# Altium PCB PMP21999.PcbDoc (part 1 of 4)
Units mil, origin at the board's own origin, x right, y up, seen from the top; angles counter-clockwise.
Board outline 7450 x 5800 mil, 6 copper layers (Top Layer, Signal Layer 3, Signal Layer 1, Signal Layer 2, Signal Layer 4, Bottom Layer), stack 66 mil thick; 237 components, 96 nets, 712 pads, 268 vias.
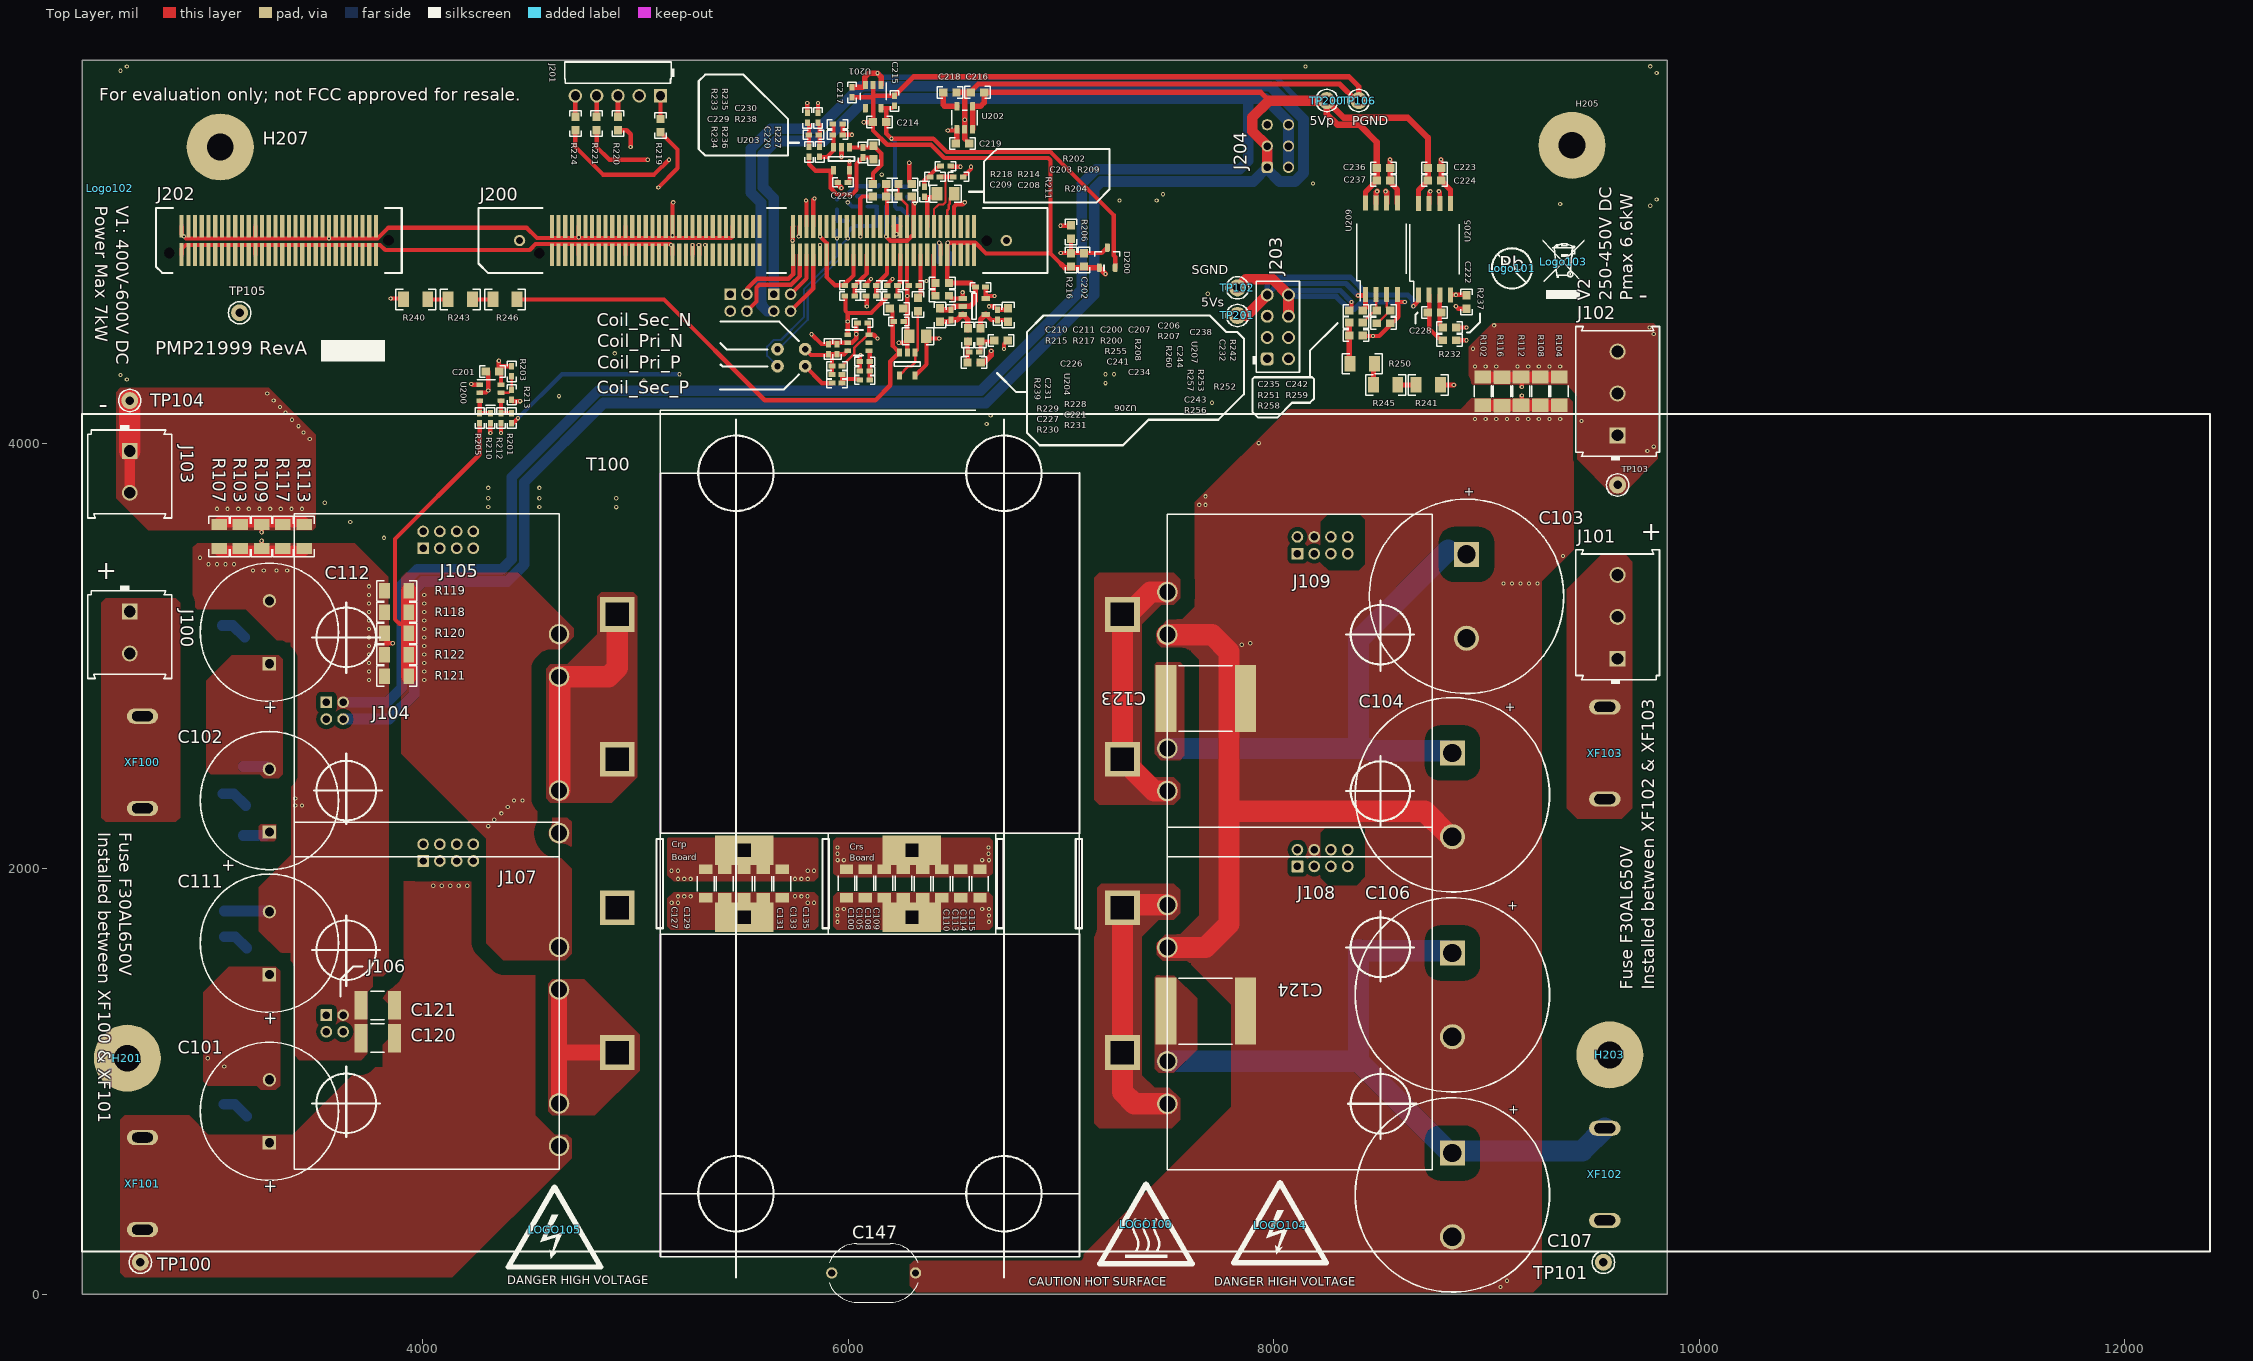
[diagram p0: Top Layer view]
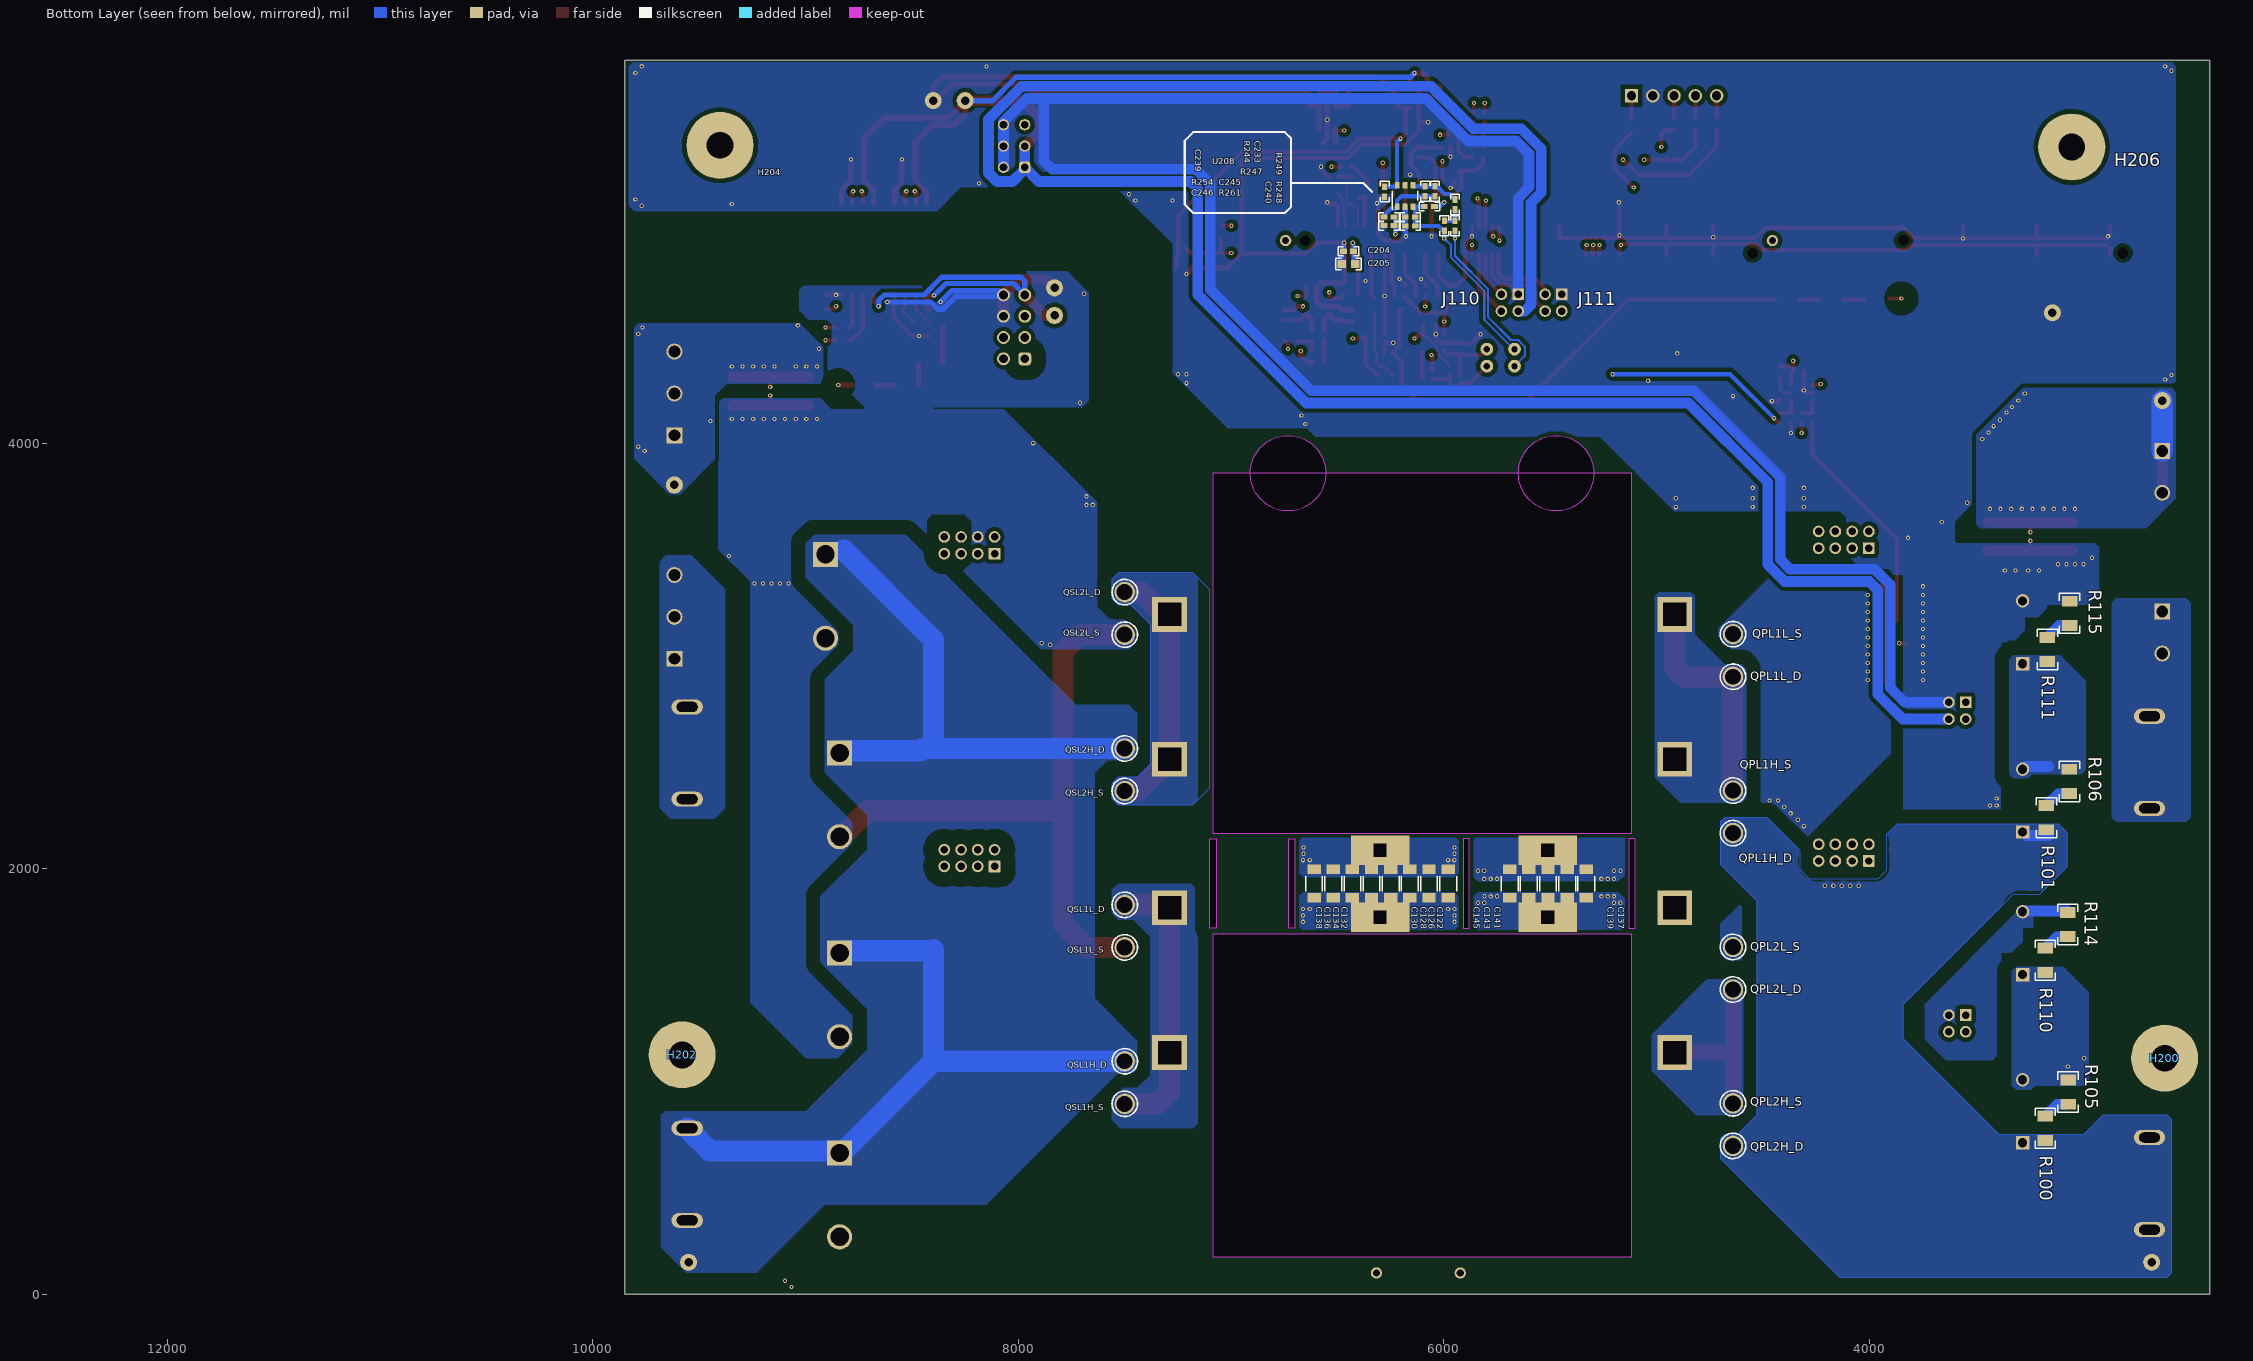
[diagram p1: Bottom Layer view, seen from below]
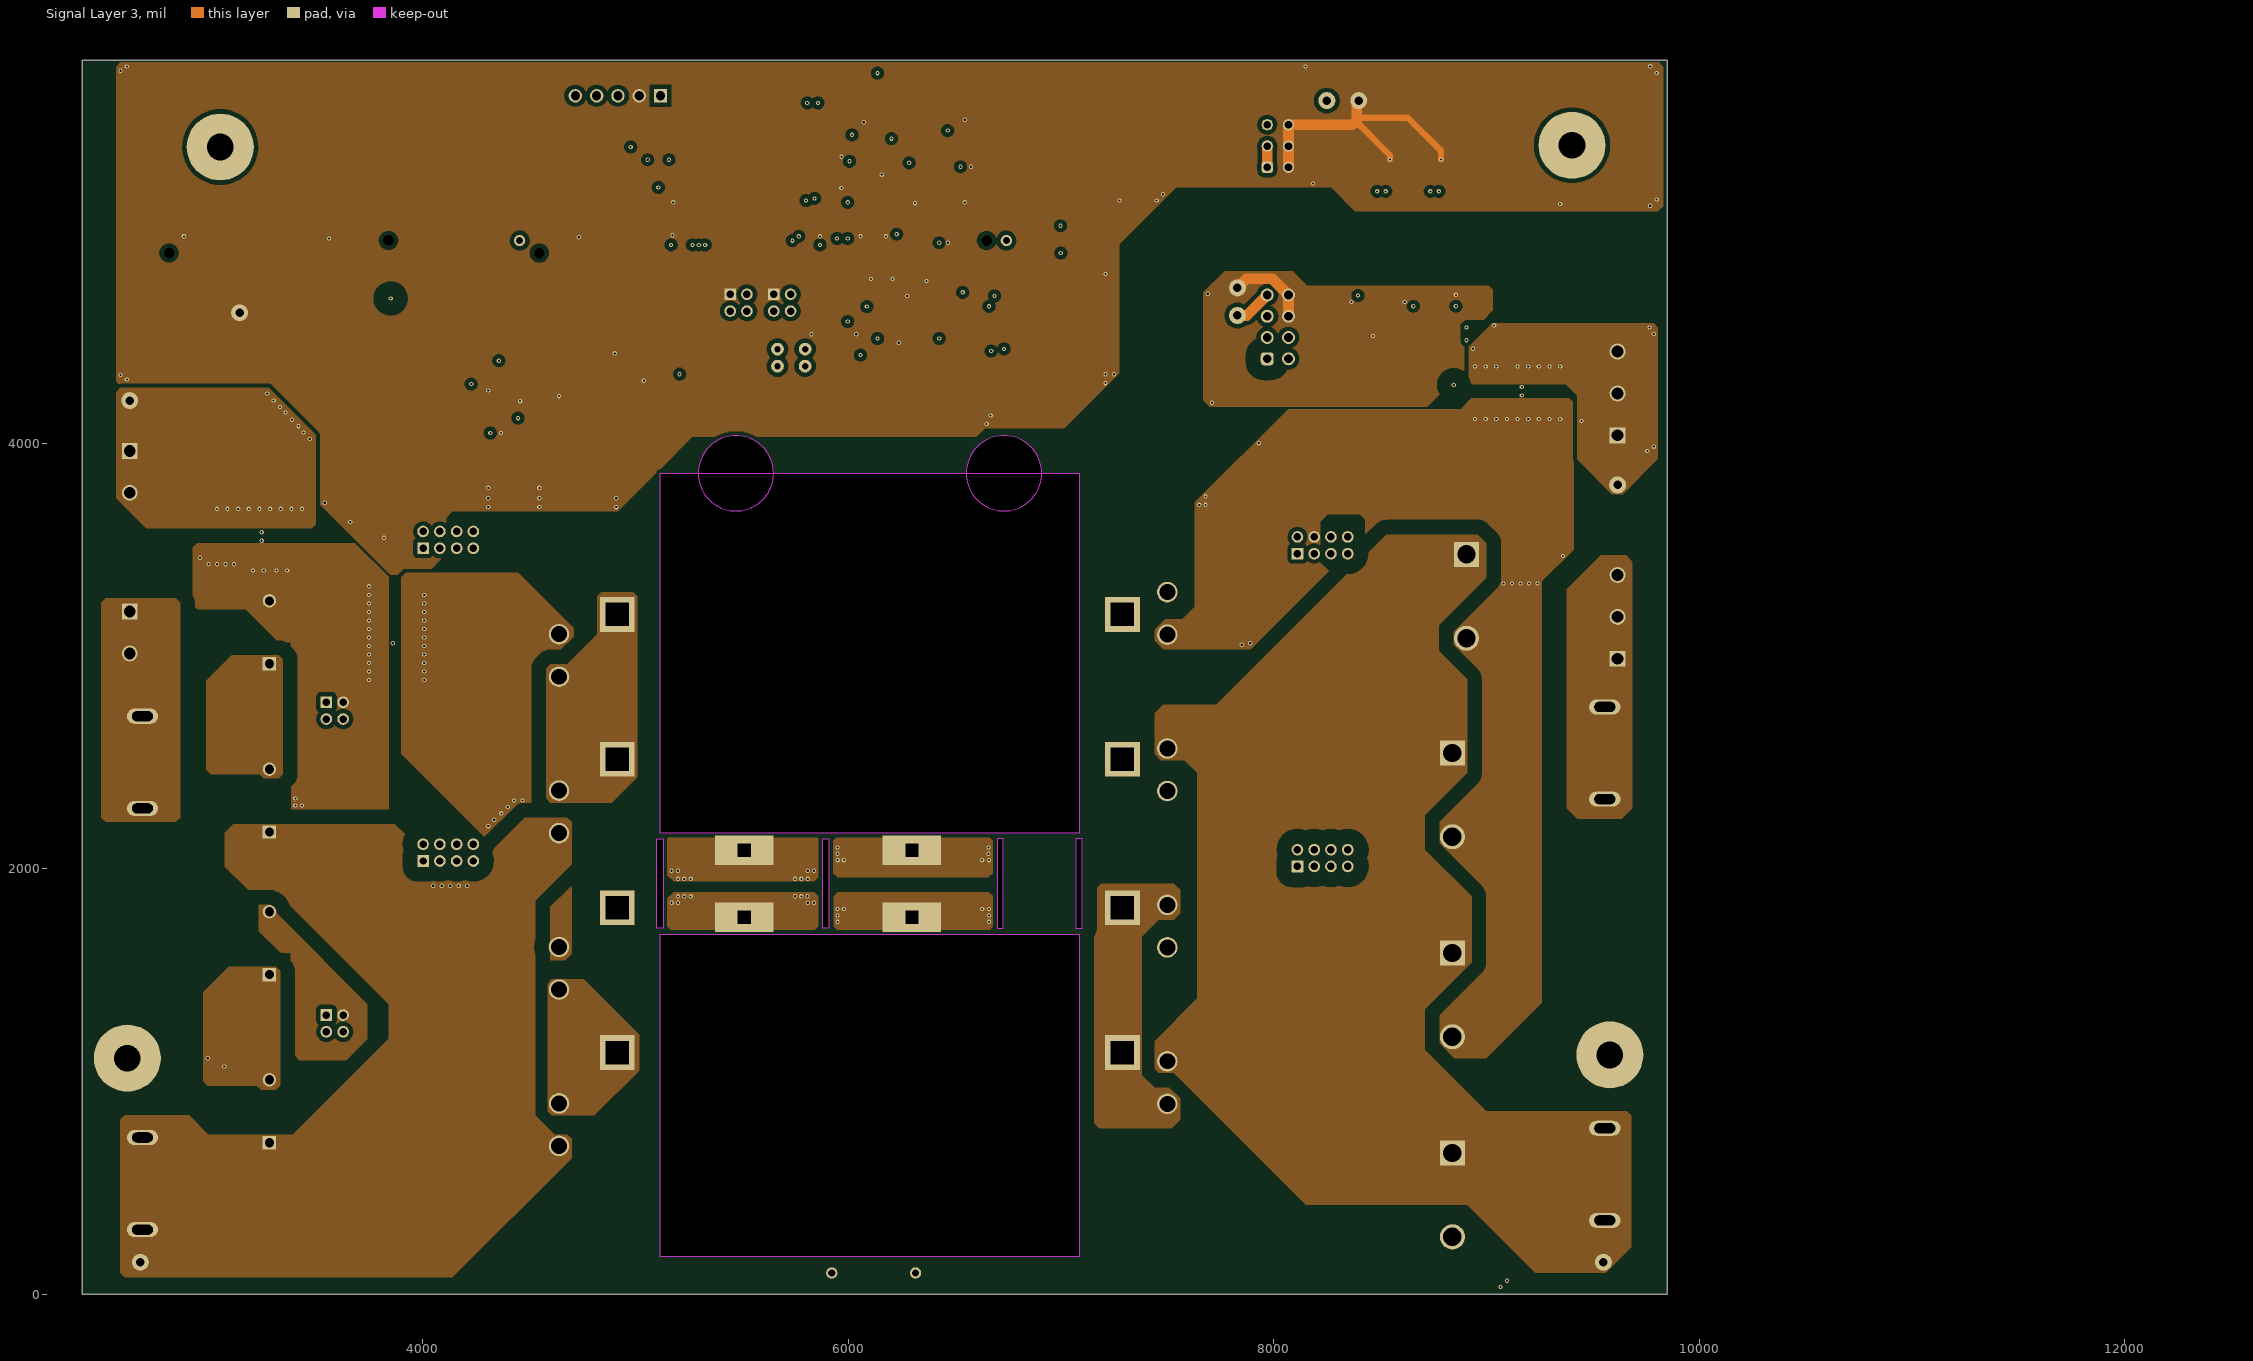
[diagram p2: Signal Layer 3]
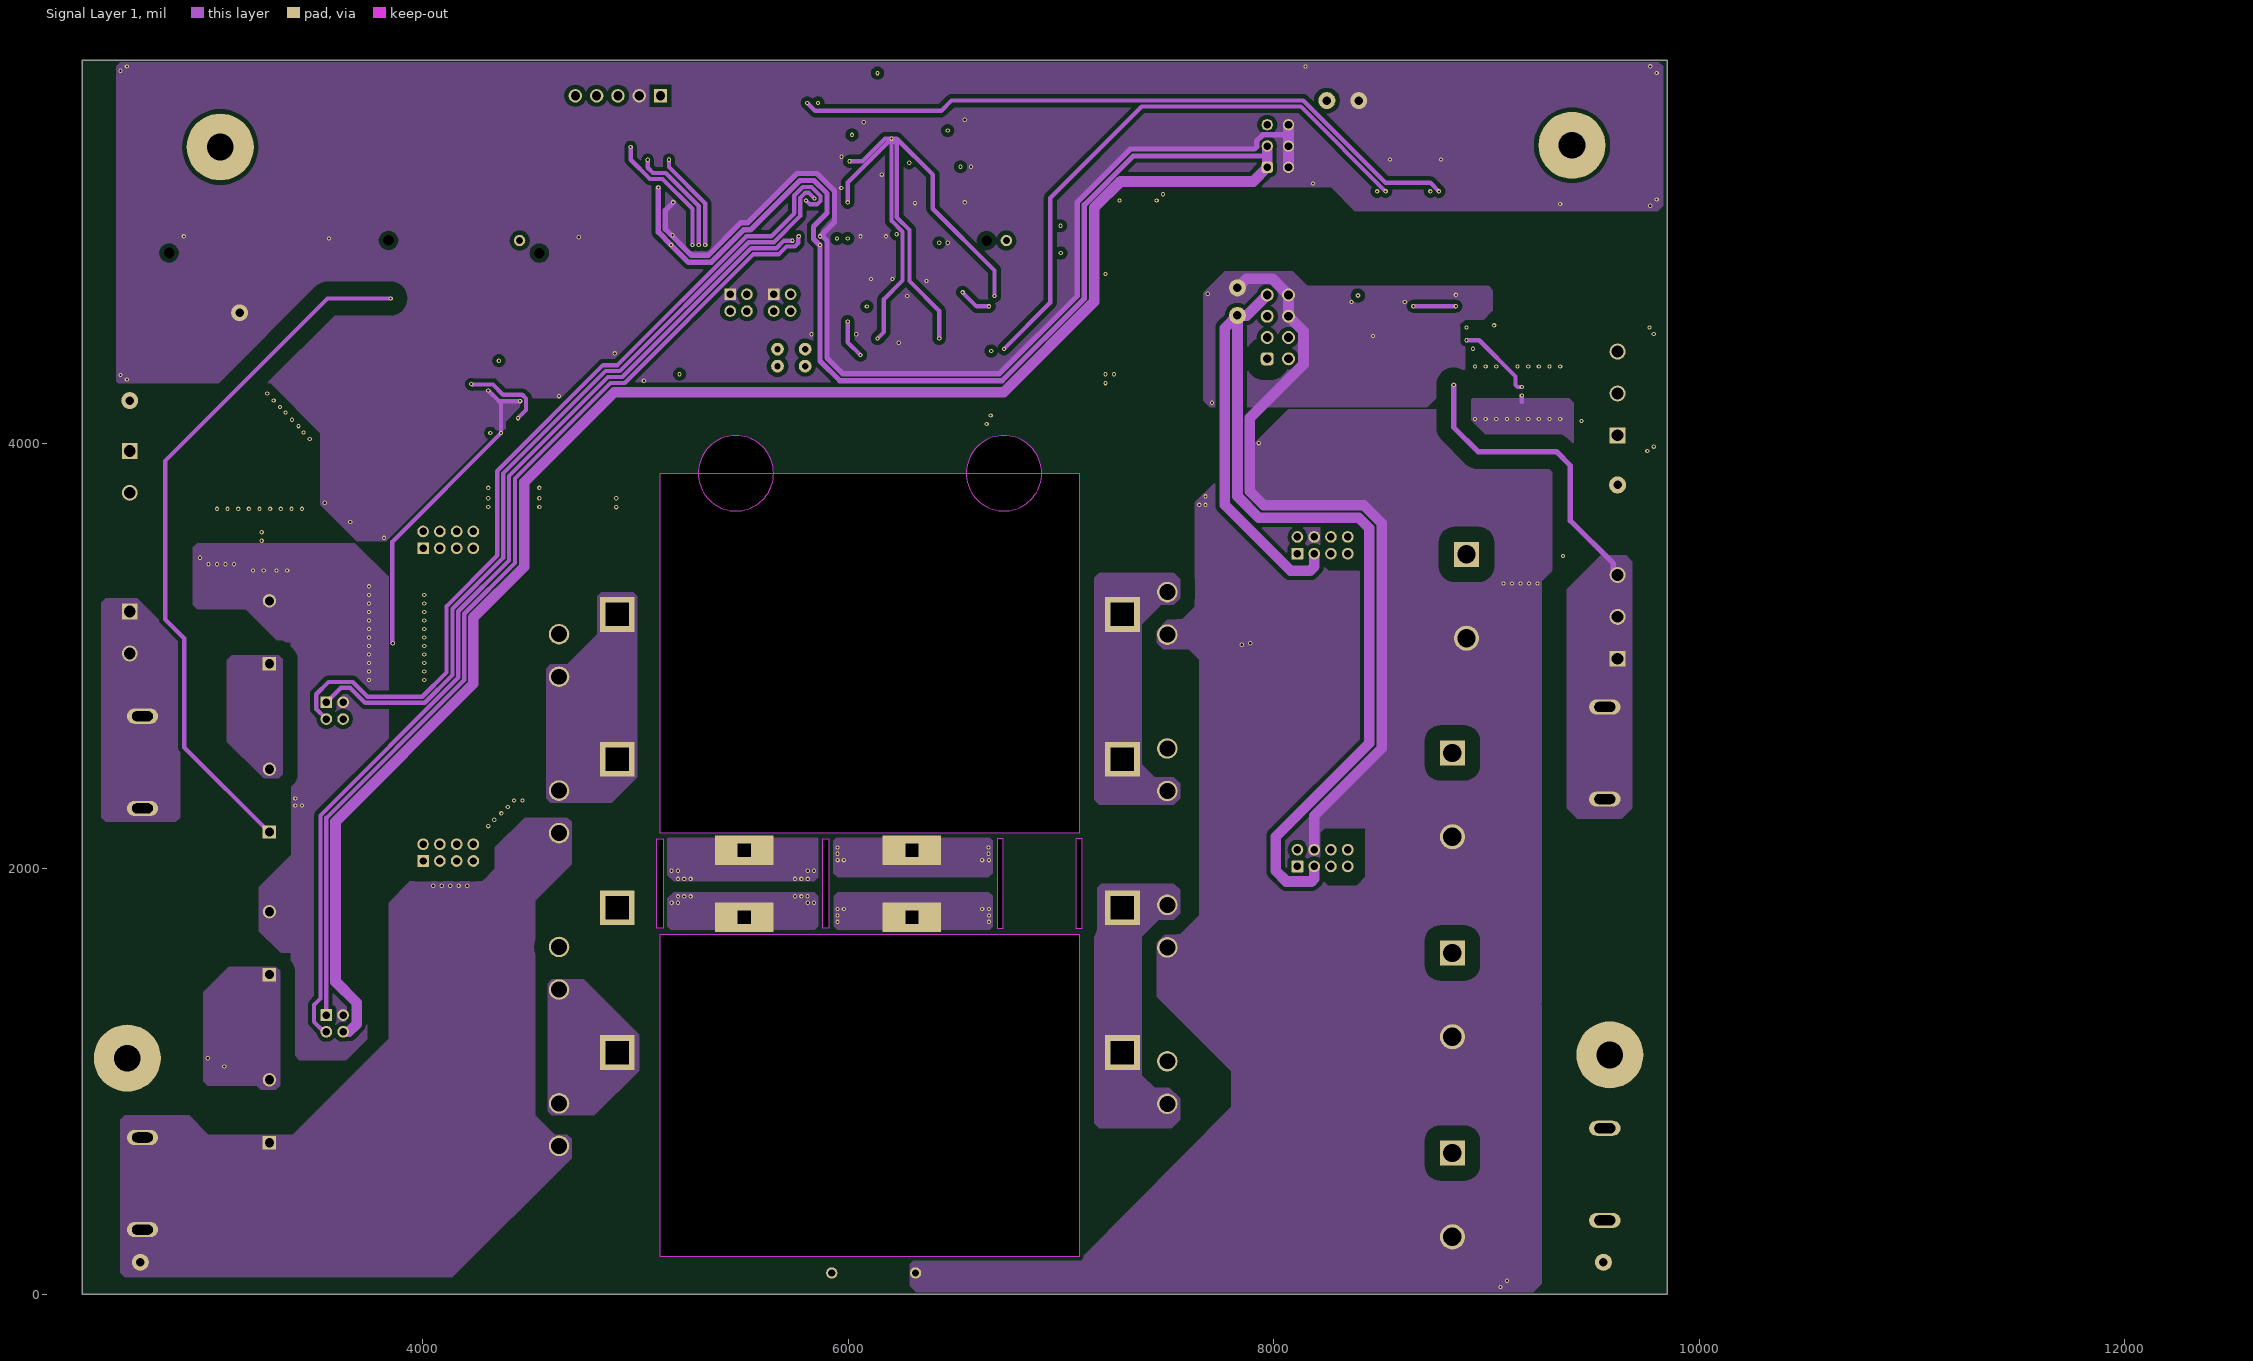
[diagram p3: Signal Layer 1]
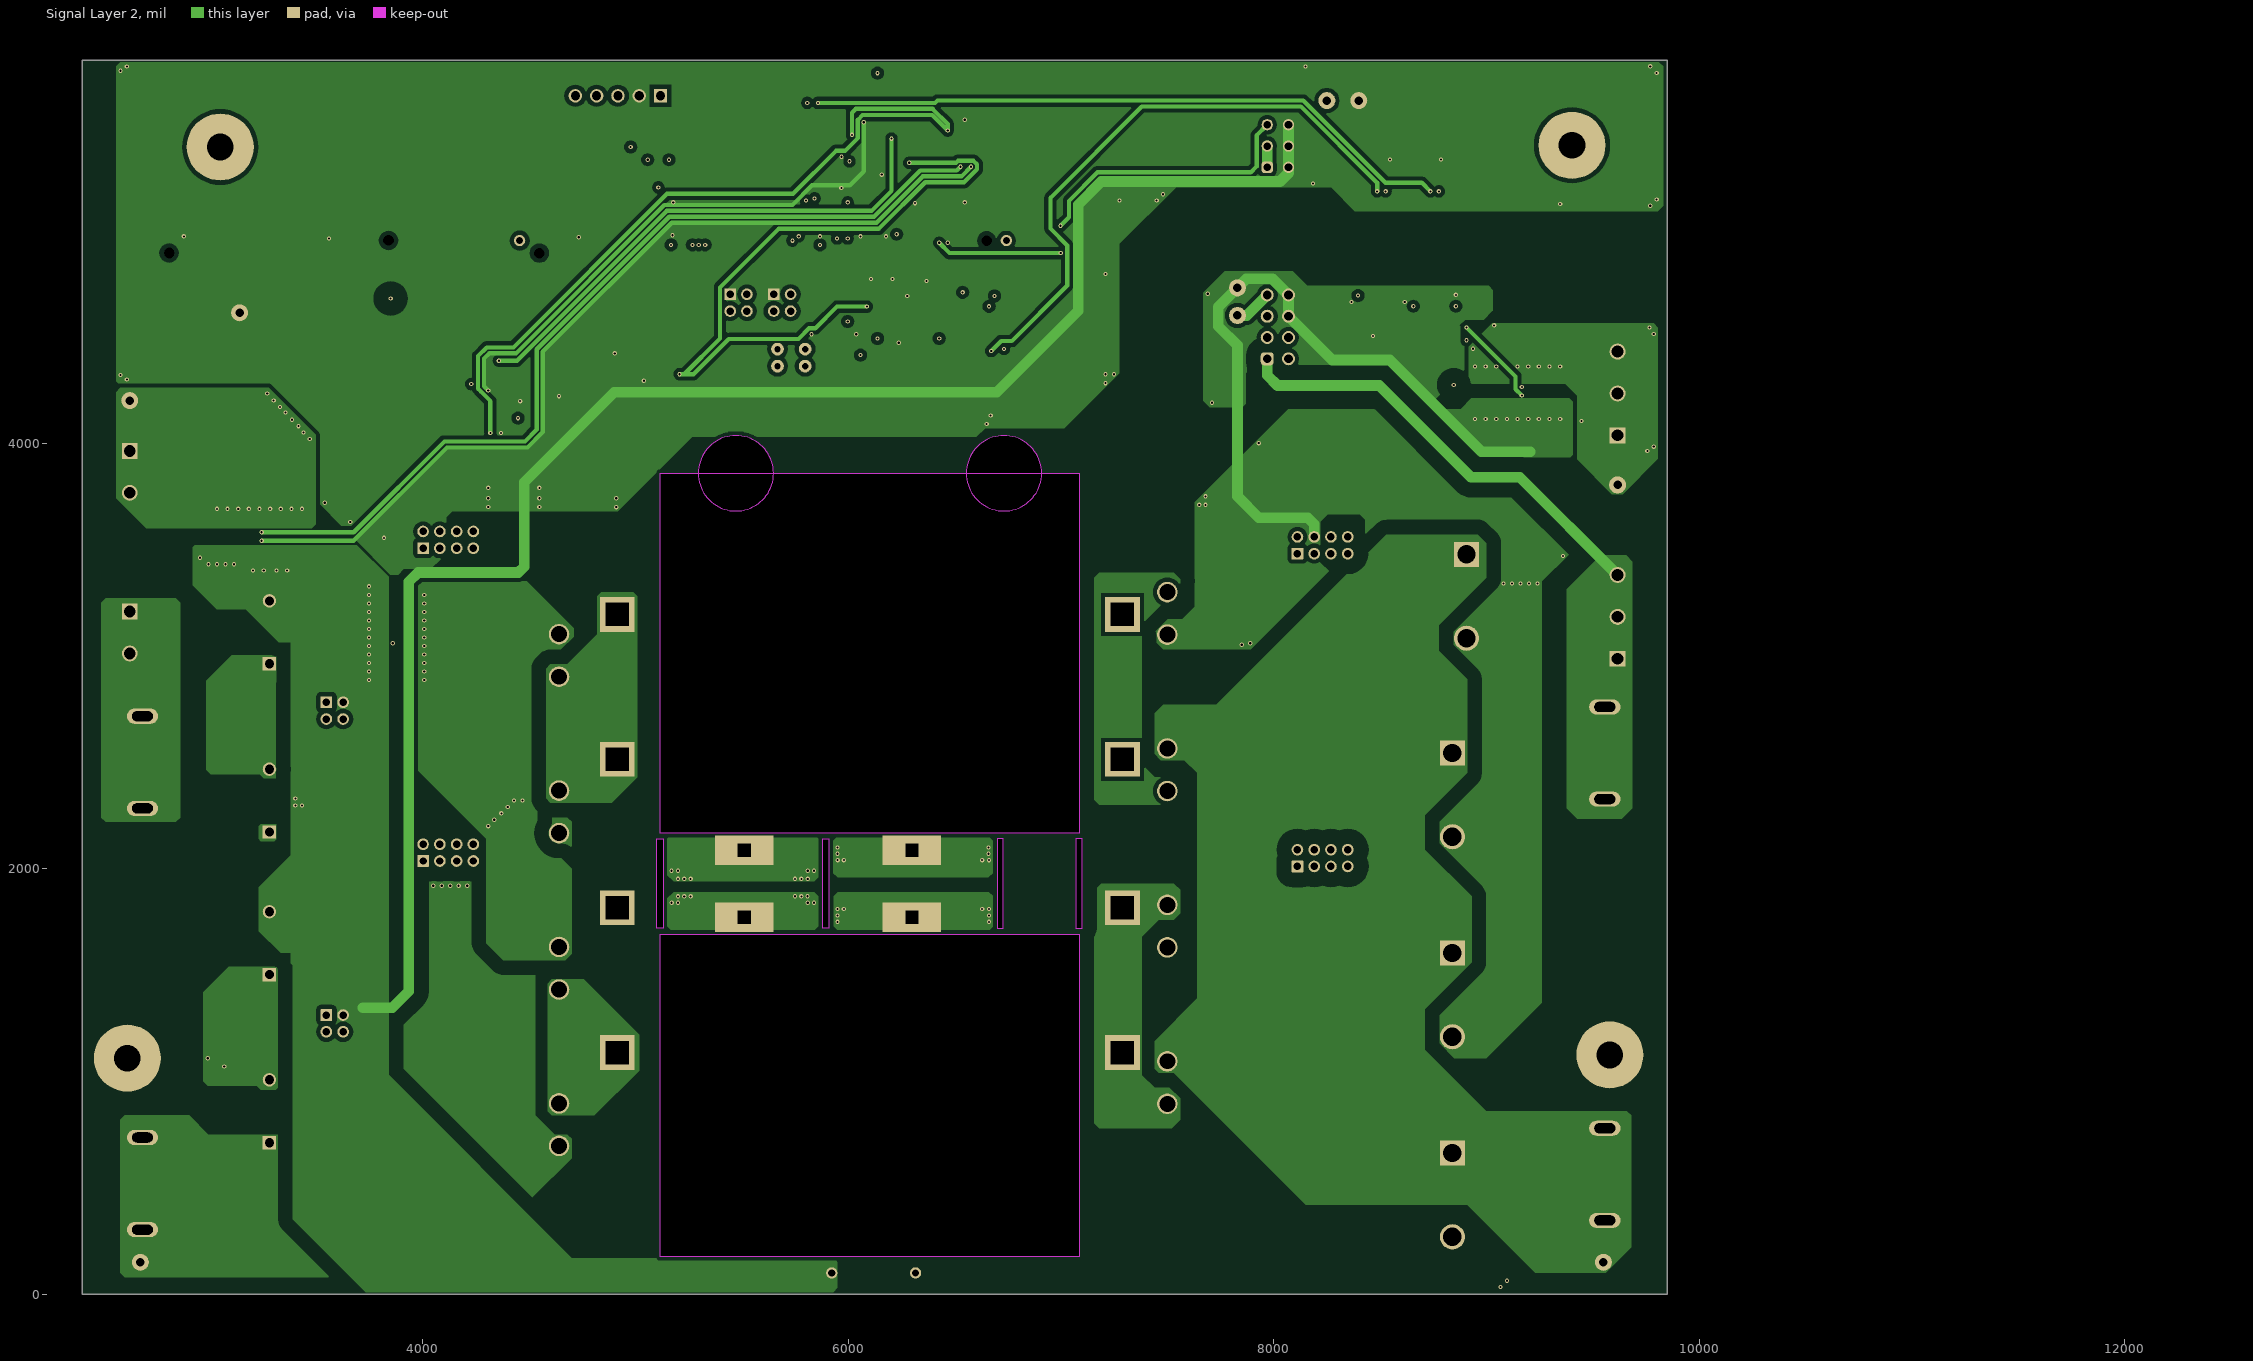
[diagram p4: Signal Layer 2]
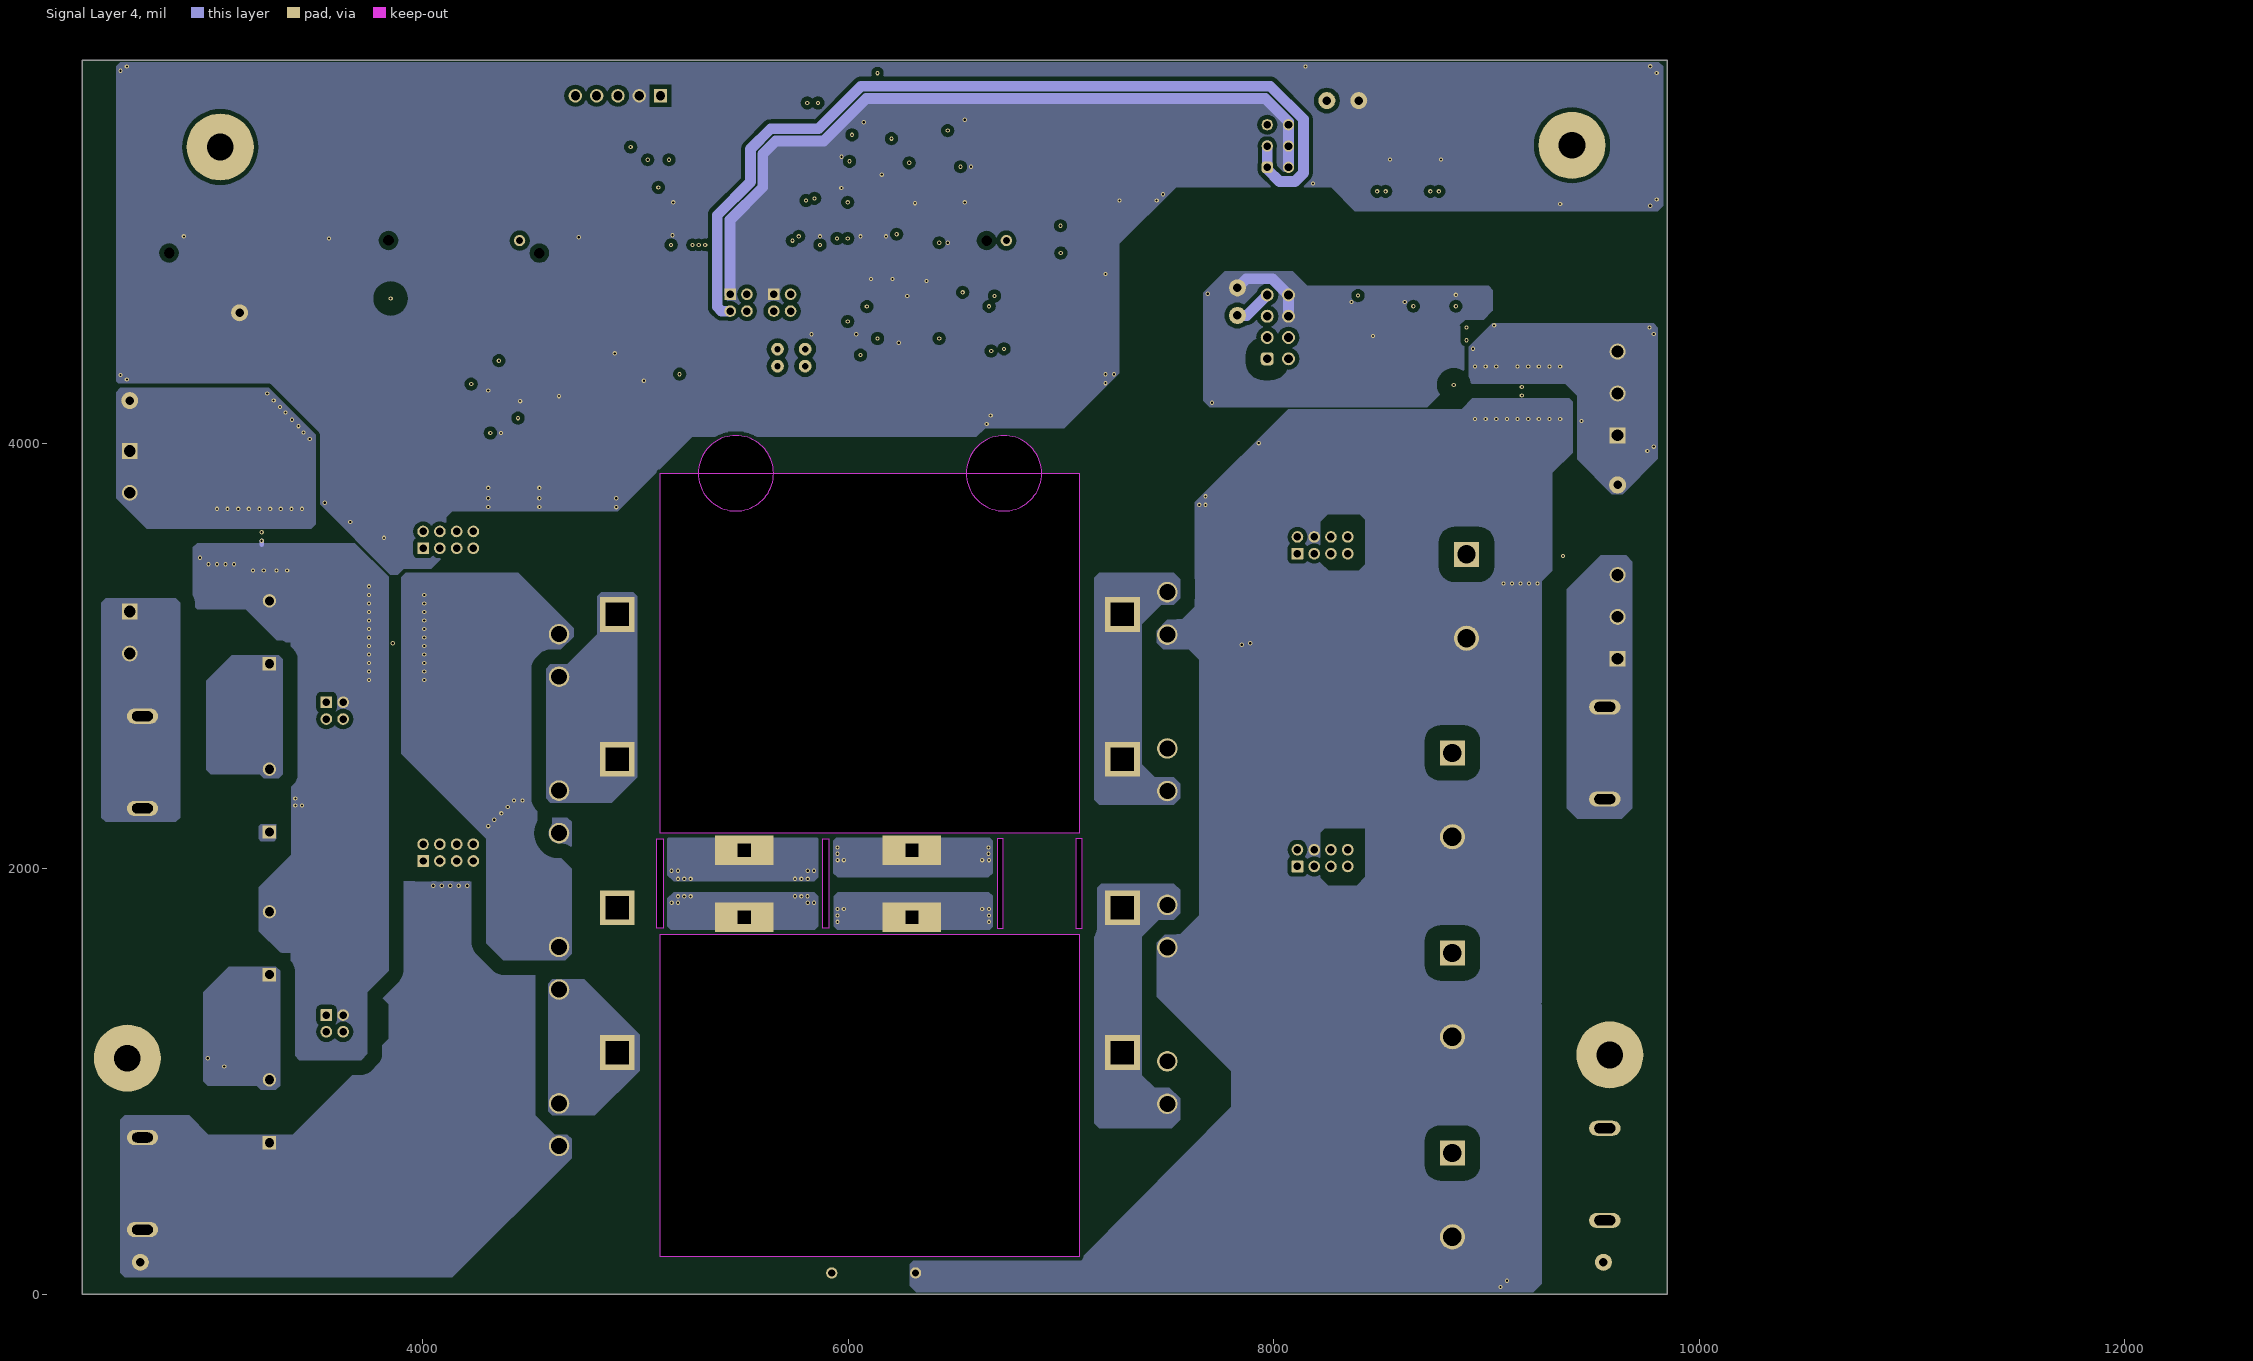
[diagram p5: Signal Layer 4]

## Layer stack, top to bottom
Top Solder: solder mask 0.4, Solder Resist, Dk 3.5
Top Layer: signal copper 4.2
Dielectric1: prepreg 8, Dk 4.2
Signal Layer 3: signal copper 1.4
Dielectric 4: core 14, FR-4, Dk 4.2
Signal Layer 1: signal copper 1.4
Dielectric 2: prepreg 8, Dk 4.2
Signal Layer 2: signal copper 1.4
Dielectric 5: core 14, FR-4, Dk 4.2
Signal Layer 4: signal copper 1.4
Dielectric 3: prepreg 8, Dk 4.2
Bottom Layer: signal copper 4.2
Bottom Solder: solder mask 0.4, Solder Resist, Dk 3.5

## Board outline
2400,0 2400,5800 9850,5800 9850,0
cut-out: 6555.12,3858.27 ccw(c6732.28,3858.27) 6732.28,3681.1 ccw(c6732.28,3858.27) 6909.45,3858.27 ccw(c6732.28,3858.27) 6732.28,4035.43 ccw(c6732.28,3858.27)
cut-out: 5295.28,3858.27 ccw(c5472.44,3858.27) 5472.44,3681.1 ccw(c5472.44,3858.27) 5649.61,3858.27 ccw(c5472.44,3858.27) 5472.44,4035.43 ccw(c5472.44,3858.27)
cut-out: 6700,1720 6730,1720 6730,2140 6700,2140
cut-out: 5880,1720 5880,2140 5910,2140 5910,1720
cut-out: 7070,1720 7100,1720 7100,2140 7070,2140
cut-out: 5100,1720 5100,2140 5130,2140 5130,1720
cut-out: 5118.11,2165.35 5118.11,3858.27 7086.61,3858.27 7086.61,2165.35
cut-out: 5118.11,177.17 5118.11,1692.91 7086.61,1692.91 7086.61,177.17

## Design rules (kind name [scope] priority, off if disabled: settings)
AcuteAngle [All] p1: minimum=4.50000000000000E+0001 checktracksonly=FALSE
AssemblyTestPointUsage [All] p1: valid=2
Clearance Clearance_2 [InNetClass('HV') vs Not InNetClass('HV')] p1: gap=70 ignorepadtopadclearanceinfootprint=FALSE
Clearance Clearance_1 [InNetClass('MV') vs Not InNetClass('MV')] p2: gap=40 ignorepadtopadclearanceinfootprint=FALSE
Clearance Clearance_Keepouts [((IsTrack Or IsArc) And Not InPoly) And IsFree and IsKeepOut vs ((IsTrack Or IsArc) And Not InPoly) And IsFree and IsKeepOut] p3: gap=0 ignorepadtopadclearanceinfootprint=FALSE
Clearance Clearance_BoardEdge_MountingHoles [OnCopper and InComponentClass('Mounting Holes') vs IsKeepOut] p4: gap=40 ignorepadtopadclearanceinfootprint=FALSE except(0: Arc-Hole Track-Hole SMDPad-Hole THPad-Hole Via-Hole Fill-Hole Poly-Hole Region-Hole Text-Hole)
Clearance Clearance_BoardEdge_Poly [OnCopper and InPoly vs IsKeepOut] p5: gap=25 ignorepadtopadclearanceinfootprint=FALSE except(0: Arc-Hole Track-Hole SMDPad-Hole THPad-Hole Via-Hole Fill-Hole Poly-Hole Region-Hole Text-Hole)
Clearance Clearance_BoardEdge [OnCopper and Not InComponentClass('Logo') and not InComponentClass('FiducialMark') and not InRegion(1000,500,4000,800) and Not IsKeepout vs IsKeepOut] p6: gap=75 ignorepadtopadclearanceinfootprint=FALSE
Clearance Clearance_Poly [InPolygon] p7: gap=20 ignorepadtopadclearanceinfootprint=FALSE except(0: Arc-Hole Track-Hole SMDPad-Hole THPad-Hole Via-Hole Fill-Hole Poly-Hole Region-Hole Text-Hole)
Clearance [All] p8: gap=7.87 ignorepadtopadclearanceinfootprint=FALSE except(0: Arc-Hole Track-Hole SMDPad-Hole THPad-Hole Via-Hole Fill-Hole Poly-Hole Region-Hole Text-Hole)
ComponentClearance ComponentClearance_MountingHoles_FiducialMarks [InComponentClass('Mounting Holes') vs InComponentClass('FiducialMark')] p1: gap=20 collisioncheckmode=3 verticalgap=10 showdistances=FALSE
ComponentClearance ComponentClearance_Shunt [InComponentClass('Header') vs InComponentClass('Shunt')] p2: gap=0 collisioncheckmode=3 verticalgap=0 showdistances=FALSE
ComponentClearance ComponentClearance_Logo [InComponentClass('Logo')] p3: gap=5 collisioncheckmode=3 verticalgap=10 showdistances=FALSE
ComponentClearance ComponentClearance_ScrewToNut [(HasFootprint('NY PMS 440 0025 PH')) vs (HasFootprint('Keystone_1902C'))] p4: gap=20 collisioncheckmode=3 verticalgap=100000 showdistances=FALSE
ComponentClearance ComponentClearance_MountingHoles [InComponentClass('Mounting Holes')] p5: gap=20 collisioncheckmode=3 verticalgap=10 showdistances=FALSE
ComponentClearance ComponentClearance_SmallPassives [HasFootprint('0201*') or HasFootprint('0402*') or HasFootprint('0508') or HasFootprint('0603*') or HasFootprint('0612') or HasFootprint('0805*') or HasFootprint('0815*') or HasFootprint('0830*') or HasFootprint('1206*') or HasFootprint('1210*') or HasFootprint('1808*') or HasFootprint('1812*') or HasFootprint('1825*') or HasFootprint('2010*') or HasFootprint('2220*') or HasFootprint('2225*') or HasFootprint('2512*') or HasFootprint('2728*') or HasFootprint('3518*') vs HasFootprint('0201*') or HasFootprint('0402*') or HasFootprint('0508') or HasFootprint('0603*') or HasFootprint('0612') or HasFootprint('0805*') or HasFootprint('0815*') or HasFootprint('0830*') or HasFootprint('1206*') or HasFootprint('1210*') or HasFootprint('1808*') or HasFootprint('1812*') or HasFootprint('1825*') or HasFootprint('2010*') or HasFootprint('2220*') or HasFootprint('2225*') or HasFootprint('2512*') or HasFootprint('2728*') or HasFootprint('3518*')] p6: gap=10 collisioncheckmode=3 verticalgap=10 showdistances=FALSE
ComponentClearance ComponentClearance_THtoSMT [IsThruComponent vs IsSMTComponent] p7: gap=10 collisioncheckmode=3 verticalgap=10 showdistances=FALSE
ComponentClearance ComponentClearance_THtoTH [IsThruComponent vs IsThruComponent] p8: gap=10 collisioncheckmode=3 verticalgap=10 showdistances=FALSE
ComponentClearance [All] p9: gap=10 collisioncheckmode=3 verticalgap=10 showdistances=FALSE
DiffPairsRouting [All] p1: maxlimit=100 minlimit=10 mostfreqgap=10 toplayer_minwidth=15 toplayer_maxwidth=15 toplayer_prefwidth=15 midlayer1_minwidth=15 midlayer1_maxwidth=15 midlayer1_prefwidth=15 midlayer2_minwidth=15 midlayer2_maxwidth=15 midlayer2_prefwidth=15 midlayer3_minwidth=15 midlayer3_maxwidth=15 midlayer3_prefwidth=15 midlayer4_minwidth=15 midlayer4_maxwidth=15 midlayer4_prefwidth=15 bottomlayer_minwidth=15 bottomlayer_maxwidth=15 bottomlayer_prefwidth=15 maxuncoupledlength=1000
FabricationTestPointUsage TestPointUsage [All] p1: valid=2 allowmultiple=FALSE
FabricationTestpoint Testpoint [All] p1: side=3 testpointundercomponent=TRUE minsize=40 maxsize=100 preferedsize=60 minholesize=0 maxholesize=40 preferedholesize=32 testpointgrid=1 allowsidetop=TRUE allowsidebottom=TRUE usegrid=TRUE gridtolerance=0.01
FanoutControl Fanout_LCC [IsLCC] p1: bgadir=Out bgaviamode=Centered fanoutstyle=Auto fanoutdirection=Alternating viagrid=1 // Fanout_LCC (Default Rule)
FanoutControl Fanout_BGA [IsBGA] p2: bgadir=Out bgaviamode=Centered fanoutstyle=Auto fanoutdirection=Alternating viagrid=1 // Fanout_BGA (Default Rule)
FanoutControl Fanout_Default [All] p4: bgadir=Out bgaviamode=Centered fanoutstyle=Auto fanoutdirection=Alternating viagrid=1 // Fanout_Default (Default Rule)
FanoutControl Fanout_Small [(CompPinCount < 5)] p5: bgadir=Out bgaviamode=Centered fanoutstyle=Auto fanoutdirection=OutThenIn viagrid=1 // Fanout_Small (Default Rule)
Height [All] p1: minheight=0 maxheight=3000 prefheight=500
HoleSize [All] p1: absolutevalues=TRUE maxlimit=251 minlimit=7 maxpercent=80.000 minpercent=20.000
MinimumAnnularRing MinimumAnnularRing_ThermalPadVias [IsVia and InAnyComponent] p1: minimumring=5.91
MinimumAnnularRing [All] p2: minimumring=4.9
MinimumSolderMaskSliver MinimumSolderMaskSliver_Logo [InComponentClass('Logo') vs InComponentClass('Logo')] p1: minsoldermaskwidth=0.7
MinimumSolderMaskSliver [All] p2: minsoldermaskwidth=2
PlaneConnect [All] p1: planeconnectstyle=Direct reliefexpansion=10 reliefentries=4 reliefconductorwidth=10 reliefairgap=10
PolygonConnect PolygonConnect_29 [All vs IsNamedPolygon('TOP_LAYER_CRP_1_P270') Or  IsNamedPolygon('C101_2') Or  IsNamedPolygon('TOP_LAYER_NETC127_1_P250') Or  IsNamedPolygon('BOTTOM_LAYER_CRP_1_P260') Or  IsNamedPolygon('Crs_1') Or  IsNamedPolygon('RTN') Or  IsNamedPolygon('VBUS') Or  IsNamedPolygon('Vout') Or  IsNamedPolygon('LEG_1_SEC') Or  IsNamedPolygon('SIGNAL_LAYER_1_NETC127_1_P252') Or  IsNamedPolygon('CS') Or  IsNamedPolygon('VBUS') Or  IsNamedPolygon('C101_2') Or  IsNamedPolygon('Leg_2_Prim') Or  IsNamedPolygon('VBUS') Or  IsNamedPolygon('Leg_1_Prim') Or  IsNamedPolygon('RTN') Or  IsNamedPolygon('C100_2') Or  IsNamedPolygon('LEG_2_SEC') Or  IsNamedPolygon('C102_2') Or  IsNamedPolygon('VBUS') Or  IsNamedPolygon('C102_2') Or  IsNamedPolygon('C102_2') Or  IsNamedPolygon('SIGNAL_LAYER_3_CRP_1_P268') Or  IsNamedPolygon('LEG_1_SEC') Or  IsNamedPolygon('Crs_1') Or  IsNamedPolygon('C102_2') Or  IsNamedPolygon('Crs_1') Or  IsNamedPolygon('CS') Or  IsNamedPolygon('RTN') Or  IsNamedPolygon('Leg_1_Prim') Or  IsNamedPolygon('PGND') Or  IsNamedPolygon('VBATT') Or  IsNamedPolygon('PGND') Or  IsNamedPolygon('Leg_2_Prim') Or  IsNamedPolygon('VBUS') Or  IsNamedPolygon('C101_2') Or  IsNamedPolygon('LEG_1_SEC') Or  IsNamedPolygon('SIGNAL_LAYER_3_NETC127_1_P246') Or  IsNamedPolygon('SIGNAL_LAYER_2_NETC127_1_P248') Or  IsNamedPolygon('Leg_1_Prim') Or  IsNamedPolygon('C101_2') Or  IsNamedPolygon('C100_2') Or  IsNamedPolygon('Crs_1') Or  IsNamedPolygon('Leg_2_Prim') Or  IsNamedPolygon('C100_2') Or  IsNamedPolygon('LEG_1_SEC') Or  IsNamedPolygon('Leg_1_Prim') Or  IsNamedPolygon('LEG_1_SEC') Or  IsNamedPolygon('C102_2') Or  IsNamedPolygon('C100_2') Or  IsNamedPolygon('SIGNAL_LAYER_1_CRP_1_P266') Or  IsNamedPolygon('Crs_1') Or  IsNamedPolygon('C102_2') Or  IsNamedPolygon('C101_2') Or  IsNamedPolygon('PGND') Or  IsNamedPolygon('Leg_2_Prim') Or  IsNamedPolygon('C101_2') Or  IsNamedPolygon('HVBUS') Or  IsNamedPolygon('C101_2') Or  IsNamedPolygon('C100_2') Or  IsNamedPolygon('Leg_2_Prim') Or  IsNamedPolygon('BATT_RTN') Or  IsNamedPolygon('SIGNAL_LAYER_4_NETC127_1_P256') Or  IsNamedPolygon('PGND') Or  IsNamedPolygon('C100_2') Or  IsNamedPolygon('SIGNAL_LAYER_4_CRP_1_P262') Or  IsNamedPolygon('RTN') Or  IsNamedPolygon('BOTTOM_LAYER_NETC127_1_P254') Or  IsNamedPolygon('VBUS') Or  IsNamedPolygon('Leg_2_Prim') Or  IsNamedPolygon('Vout') Or  IsNamedPolygon('Leg_1_Prim') Or  IsNamedPolygon('RTN') Or  IsNamedPolygon('Crs_1') Or  IsNamedPolygon('CS') Or  IsNamedPolygon('HVBUS') Or  IsNamedPolygon('Vout') Or  IsNamedPolygon('SIGNAL_LAYER_2_CRP_1_P264') Or  IsNamedPolygon('LEG_1_SEC') Or  IsNamedPolygon('Leg_1_Prim')] p1: connectstyle=Direct reliefconductorwidth=10 reliefentries=4 polygonreliefangle="90 Angle" airgapwidth=10
PolygonConnect PolygonConnect_28 [All vs IsNamedPolygon('C101_2') Or  IsNamedPolygon('C101_2') Or  IsNamedPolygon('SIGNAL_LAYER_1_NETC127_1_P252') Or  IsNamedPolygon('TOP_LAYER_NETC127_1_P250') Or  IsNamedPolygon('VBUS') Or  IsNamedPolygon('CS') Or  IsNamedPolygon('HVBUS') Or  IsNamedPolygon('C100_2') Or  IsNamedPolygon('SIGNAL_LAYER_4_CRP_1_P262') Or  IsNamedPolygon('PGND') Or  IsNamedPolygon('C100_2') Or  IsNamedPolygon('PGND') Or  IsNamedPolygon('PGND') Or  IsNamedPolygon('Leg_1_Prim') Or  IsNamedPolygon('Leg_1_Prim') Or  IsNamedPolygon('C102_2') Or  IsNamedPolygon('VBUS') Or  IsNamedPolygon('C100_2') Or  IsNamedPolygon('C100_2') Or  IsNamedPolygon('Leg_1_Prim') Or  IsNamedPolygon('Leg_1_Prim') Or  IsNamedPolygon('Crs_1') Or  IsNamedPolygon('VBUS') Or  IsNamedPolygon('Leg_1_Prim') Or  IsNamedPolygon('SIGNAL_LAYER_3_CRP_1_P268') Or  IsNamedPolygon('Crs_1') Or  IsNamedPolygon('Leg_2_Prim') Or  IsNamedPolygon('VBUS') Or  IsNamedPolygon('TOP_LAYER_CRP_1_P270') Or  IsNamedPolygon('Leg_2_Prim') Or  IsNamedPolygon('C101_2') Or  IsNamedPolygon('Leg_2_Prim') Or  IsNamedPolygon('SIGNAL_LAYER_2_NETC127_1_P248') Or  IsNamedPolygon('BOTTOM_LAYER_CRP_1_P260') Or  IsNamedPolygon('VBATT') Or  IsNamedPolygon('Leg_2_Prim') Or  IsNamedPolygon('Crs_1') Or  IsNamedPolygon('SIGNAL_LAYER_1_CRP_1_P266') Or  IsNamedPolygon('VBUS') Or  IsNamedPolygon('Crs_1') Or  IsNamedPolygon('SIGNAL_LAYER_3_NETC127_1_P246') Or  IsNamedPolygon('Crs_1') Or  IsNamedPolygon('HVBUS') Or  IsNamedPolygon('CS') Or  IsNamedPolygon('SIGNAL_LAYER_4_NETC127_1_P256') Or  IsNamedPolygon('VBUS') Or  IsNamedPolygon('C102_2') Or  IsNamedPolygon('BATT_RTN') Or  IsNamedPolygon('Leg_2_Prim') Or  IsNamedPolygon('SIGNAL_LAYER_2_CRP_1_P264') Or  IsNamedPolygon('C100_2') Or  IsNamedPolygon('Leg_2_Prim') Or  IsNamedPolygon('CS') Or  IsNamedPolygon('C101_2') Or  IsNamedPolygon('C101_2') Or  IsNamedPolygon('C100_2') Or  IsNamedPolygon('BOTTOM_LAYER_NETC127_1_P254') Or  IsNamedPolygon('Leg_1_Prim') Or  IsNamedPolygon('Crs_1')] p2: connectstyle=Direct reliefconductorwidth=10 reliefentries=4 polygonreliefangle="90 Angle" airgapwidth=10
PolygonConnect PolygonConnect_27 [All vs IsNamedPolygon('C101_2') Or  IsNamedPolygon('Leg_1_Prim') Or  IsNamedPolygon('VBUS') Or  IsNamedPolygon('Leg_1_Prim') Or  IsNamedPolygon('VBUS') Or  IsNamedPolygon('Leg_2_Prim') Or  IsNamedPolygon('C101_2') Or  IsNamedPolygon('Leg_1_Prim') Or  IsNamedPolygon('HVBUS') Or  IsNamedPolygon('C101_2') Or  IsNamedPolygon('C102_2') Or  IsNamedPolygon('Leg_1_Prim') Or  IsNamedPolygon('Leg_2_Prim') Or  IsNamedPolygon('Leg_1_Prim') Or  IsNamedPolygon('C102_2') Or  IsNamedPolygon('PGND') Or  IsNamedPolygon('Leg_1_Prim') Or  IsNamedPolygon('HVBUS') Or  IsNamedPolygon('C101_2') Or  IsNamedPolygon('CS') Or  IsNamedPolygon('CS') Or  IsNamedPolygon('Leg_2_Prim') Or  IsNamedPolygon('PGND') Or  IsNamedPolygon('CS') Or  IsNamedPolygon('C101_2') Or  IsNamedPolygon('Leg_2_Prim') Or  IsNamedPolygon('Leg_2_Prim') Or  IsNamedPolygon('Leg_2_Prim') Or  IsNamedPolygon('PGND') Or  IsNamedPolygon('TOP_LAYER_NETC127_1_P250') Or  IsNamedPolygon('SIGNAL_LAYER_3_NETC127_1_P246') Or  IsNamedPolygon('SIGNAL_LAYER_2_NETC127_1_P248') Or  IsNamedPolygon('VBATT') Or  IsNamedPolygon('SIGNAL_LAYER_2_CRP_1_P264') Or  IsNamedPolygon('SIGNAL_LAYER_4_CRP_1_P262') Or  IsNamedPolygon('BOTTOM_LAYER_CRP_1_P260') Or  IsNamedPolygon('BATT_RTN') Or  IsNamedPolygon('VBUS') Or  IsNamedPolygon('TOP_LAYER_CRP_1_P270') Or  IsNamedPolygon('SIGNAL_LAYER_4_NETC127_1_P256') Or  IsNamedPolygon('VBUS') Or  IsNamedPolygon('SIGNAL_LAYER_1_NETC127_1_P252') Or  IsNamedPolygon('VBUS') Or  IsNamedPolygon('VBUS') Or  IsNamedPolygon('SIGNAL_LAYER_1_CRP_1_P266') Or  IsNamedPolygon('BOTTOM_LAYER_NETC127_1_P254') Or  IsNamedPolygon('SIGNAL_LAYER_3_CRP_1_P268')] p3: connectstyle=Direct reliefconductorwidth=10 reliefentries=4 polygonreliefangle="90 Angle" airgapwidth=10
PolygonConnect PolygonConnect_26 [All vs IsNamedPolygon('TOP_LAYER_CRP_1_P270') Or  IsNamedPolygon('SIGNAL_LAYER_4_CRP_1_P262') Or  IsNamedPolygon('TOP_LAYER_NETC127_1_P250') Or  IsNamedPolygon('SIGNAL_LAYER_4_NETC127_1_P256') Or  IsNamedPolygon('SIGNAL_LAYER_2_CRP_1_P264') Or  IsNamedPolygon('SIGNAL_LAYER_1_CRP_1_P266') Or  IsNamedPolygon('SIGNAL_LAYER_1_NETC127_1_P252') Or  IsNamedPolygon('SIGNAL_LAYER_3_NETC127_1_P246') Or  IsNamedPolygon('SIGNAL_LAYER_3_CRP_1_P268') Or  IsNamedPolygon('BOTTOM_LAYER_CRP_1_P260') Or  IsNamedPolygon('VBATT') Or  IsNamedPolygon('BATT_RTN') Or  IsNamedPolygon('SIGNAL_LAYER_2_NETC127_1_P248') Or  IsNamedPolygon('BOTTOM_LAYER_NETC127_1_P254')] p4: connectstyle=Direct reliefconductorwidth=10 reliefentries=4 polygonreliefangle="90 Angle" airgapwidth=10
PolygonConnect PolygonConnect_25 [All vs IsNamedPolygon('BATT_RTN') Or  IsNamedPolygon('BOTTOM_LAYER_NETC127_1_P254') Or  IsNamedPolygon('TOP_LAYER_NETC127_1_P250') Or  IsNamedPolygon('SIGNAL_LAYER_2_NETC127_1_P248') Or  IsNamedPolygon('SIGNAL_LAYER_3_NETC127_1_P246') Or  IsNamedPolygon('SIGNAL_LAYER_1_NETC127_1_P252') Or  IsNamedPolygon('SIGNAL_LAYER_4_NETC127_1_P256') Or  IsNamedPolygon('VBATT')] p5: connectstyle=Direct reliefconductorwidth=10 reliefentries=4 polygonreliefangle="90 Angle" airgapwidth=10
PolygonConnect PolygonConnect_24 [All vs IsNamedPolygon('SIGNAL_LAYER_3_NETC127_1_P246')] p6: connectstyle=Direct reliefconductorwidth=10 reliefentries=4 polygonreliefangle="90 Angle" airgapwidth=10
PolygonConnect PolygonConnect_23 [All vs IsNamedPolygon('RTN') Or  IsNamedPolygon('CS') Or  IsNamedPolygon('C122_1') Or  IsNamedPolygon('C122_1') Or  IsNamedPolygon('C102_2') Or  IsNamedPolygon('VBUS') Or  IsNamedPolygon('HVBUS') Or  IsNamedPolygon('Q101_2') Or  IsNamedPolygon('Q101_2') Or  IsNamedPolygon('C103_1') Or  IsNamedPolygon('C122_2') Or  IsNamedPolygon('VBATT') Or  IsNamedPolygon('BATT_RTN') Or  IsNamedPolygon('SGND') Or  IsNamedPolygon('C100_1') Or  IsNamedPolygon('C122_2') Or  IsNamedPolygon('PGND') Or  IsNamedPolygon('C100_1') Or  IsNamedPolygon('PGND') Or  IsNamedPolygon('C103_1') Or  IsNamedPolygon('C103_1') Or  IsNamedPolygon('C103_1') Or  IsNamedPolygon('J105_1') Or  IsNamedPolygon('VBATT') Or  IsNamedPolygon('BATT_RTN') Or  IsNamedPolygon('J105_1') Or  IsNamedPolygon('HVBUS') Or  IsNamedPolygon('Q101_2') Or  IsNamedPolygon('RTN') Or  IsNamedPolygon('C102_2') Or  IsNamedPolygon('C102_2') Or  IsNamedPolygon('CS') Or  IsNamedPolygon('C103_1') Or  IsNamedPolygon('C102_2') Or  IsNamedPolygon('C100_2') Or  IsNamedPolygon('C100_2') Or  IsNamedPolygon('5Vs') Or  IsNamedPolygon('VBUS') Or  IsNamedPolygon('VBUS') Or  IsNamedPolygon('J105_1') Or  IsNamedPolygon('J105_1') Or  IsNamedPolygon('J105_1') Or  IsNamedPolygon('VBUS') Or  IsNamedPolygon('VBUS') Or  IsNamedPolygon('J105_1') Or  IsNamedPolygon('C100_2') Or  IsNamedPolygon('C100_1') Or  IsNamedPolygon('C103_1') Or  IsNamedPolygon('C100_1') Or  IsNamedPolygon('C100_1') Or  IsNamedPolygon('C100_2') Or  IsNamedPolygon('C100_1') Or  IsNamedPolygon('C100_2') Or  IsNamedPolygon('C100_2') Or  IsNamedPolygon('C100_1') Or  IsNamedPolygon('C100_1') Or  IsNamedPolygon('PGND') Or  IsNamedPolygon('SGND') Or  IsNamedPolygon('SGND') Or  IsNamedPolygon('SGND') Or  IsNamedPolygon('SGND') Or  IsNamedPolygon('SGND') Or  IsNamedPolygon('VBATT') Or  IsNamedPolygon('SGND') Or  IsNamedPolygon('SGND') Or  IsNamedPolygon('PGND') Or  IsNamedPolygon('SGND') Or  IsNamedPolygon('SGND') Or  IsNamedPolygon('SGND') Or  IsNamedPolygon('PGND') Or  IsNamedPolygon('SGND') Or  IsNamedPolygon('VBATT') Or  IsNamedPolygon('SGND') Or  IsNamedPolygon('PGND') Or  IsNamedPolygon('PGND') Or  IsNamedPolygon('SGND') Or  IsNamedPolygon('PGND') Or  IsNamedPolygon('SGND') Or  IsNamedPolygon('SGND') Or  IsNamedPolygon('PGND') Or  IsNamedPolygon('BATT_RTN') Or  IsNamedPolygon('SGND') Or  IsNamedPolygon('SGND') Or  IsNamedPolygon('PGND') Or  IsNamedPolygon('BATT_RTN') Or  IsNamedPolygon('PGND') Or  IsNamedPolygon('PGND') Or  IsNamedPolygon('PGND') Or  IsNamedPolygon('PGND') Or  IsNamedPolygon('PGND') Or  IsNamedPolygon('PGND') Or  IsNamedPolygon('VBATT') Or  IsNamedPolygon('5Vp') Or  IsNamedPolygon('VBATT') Or  IsNamedPolygon('VBUS') Or  IsNamedPolygon('5Vp') Or  IsNamedPolygon('5Vp')] p7: connectstyle=Direct reliefconductorwidth=10 reliefentries=4 polygonreliefangle="90 Angle" airgapwidth=10
PolygonConnect PolygonConnect_22 [All vs IsNamedPolygon('PGND') Or  IsNamedPolygon('VBATT') Or  IsNamedPolygon('VBATT') Or  IsNamedPolygon('VBATT') Or  IsNamedPolygon('RTN') Or  IsNamedPolygon('PGND') Or  IsNamedPolygon('C100_1') Or  IsNamedPolygon('SGND') Or  IsNamedPolygon('VBATT') Or  IsNamedPolygon('VBUS') Or  IsNamedPolygon('VBATT') Or  IsNamedPolygon('C103_1') Or  IsNamedPolygon('PGND') Or  IsNamedPolygon('PGND') Or  IsNamedPolygon('C100_1') Or  IsNamedPolygon('VBUS') Or  IsNamedPolygon('PGND') Or  IsNamedPolygon('SGND') Or  IsNamedPolygon('PGND') Or  IsNamedPolygon('J105_1') Or  IsNamedPolygon('SGND') Or  IsNamedPolygon('C100_2') Or  IsNamedPolygon('C100_2') Or  IsNamedPolygon('C100_2') Or  IsNamedPolygon('SGND') Or  IsNamedPolygon('J105_1') Or  IsNamedPolygon('SGND') Or  IsNamedPolygon('SGND') Or  IsNamedPolygon('PGND') Or  IsNamedPolygon('J105_1') Or  IsNamedPolygon('PGND') Or  IsNamedPolygon('C100_1') Or  IsNamedPolygon('SGND') Or  IsNamedPolygon('C100_1') Or  IsNamedPolygon('SGND') Or  IsNamedPolygon('PGND') Or  IsNamedPolygon('BATT_RTN') Or  IsNamedPolygon('J105_1') Or  IsNamedPolygon('PGND') Or  IsNamedPolygon('VBUS') Or  IsNamedPolygon('SGND') Or  IsNamedPolygon('C100_1') Or  IsNamedPolygon('PGND') Or  IsNamedPolygon('J105_1') Or  IsNamedPolygon('C103_1') Or  IsNamedPolygon('SGND') Or  IsNamedPolygon('PGND') Or  IsNamedPolygon('SGND') Or  IsNamedPolygon('SGND') Or  IsNamedPolygon('SGND') Or  IsNamedPolygon('C100_2') Or  IsNamedPolygon('C100_2') Or  IsNamedPolygon('BATT_RTN') Or  IsNamedPolygon('SGND') Or  IsNamedPolygon('PGND') Or  IsNamedPolygon('C103_1') Or  IsNamedPolygon('C100_1') Or  IsNamedPolygon('VBUS') Or  IsNamedPolygon('PGND') Or  IsNamedPolygon('VBATT') Or  IsNamedPolygon('Q101_2') Or  IsNamedPolygon('C103_1') Or  IsNamedPolygon('C103_1') Or  IsNamedPolygon('PGND') Or  IsNamedPolygon('5Vp') Or  IsNamedPolygon('RTN') Or  IsNamedPolygon('C103_1') Or  IsNamedPolygon('SGND') Or  IsNamedPolygon('5Vp') Or  IsNamedPolygon('J105_1') Or  IsNamedPolygon('SGND') Or  IsNamedPolygon('SGND') Or  IsNamedPolygon('C100_1') Or  IsNamedPolygon('HVBUS') Or  IsNamedPolygon('C100_1') Or  IsNamedPolygon('BATT_RTN') Or  IsNamedPolygon('C102_2') Or  IsNamedPolygon('Q101_2') Or  IsNamedPolygon('PGND') Or  IsNamedPolygon('BATT_RTN') Or  IsNamedPolygon('SGND') Or  IsNamedPolygon('C100_2') Or  IsNamedPolygon('VBUS') Or  IsNamedPolygon('C122_1') Or  IsNamedPolygon('C102_2') Or  IsNamedPolygon('CS') Or  IsNamedPolygon('HVBUS') Or  IsNamedPolygon('CS') Or  IsNamedPolygon('C122_2') Or  IsNamedPolygon('C102_2') Or  IsNamedPolygon('VBUS') Or  IsNamedPolygon('Q101_2') Or  IsNamedPolygon('C122_2') Or  IsNamedPolygon('C122_1') Or  IsNamedPolygon('C102_2')] p8: connectstyle=Direct reliefconductorwidth=10 reliefentries=4 polygonreliefangle="90 Angle" airgapwidth=10
PolygonConnect PolygonConnect_21 [All vs IsNamedPolygon('SGND') Or  IsNamedPolygon('SGND') Or  IsNamedPolygon('SGND') Or  IsNamedPolygon('PGND') Or  IsNamedPolygon('SGND') Or  IsNamedPolygon('SGND') Or  IsNamedPolygon('PGND') Or  IsNamedPolygon('SGND') Or  IsNamedPolygon('PGND') Or  IsNamedPolygon('PGND') Or  IsNamedPolygon('SGND') Or  IsNamedPolygon('SGND') Or  IsNamedPolygon('SGND') Or  IsNamedPolygon('SGND') Or  IsNamedPolygon('SGND') Or  IsNamedPolygon('SGND') Or  IsNamedPolygon('SGND') Or  IsNamedPolygon('C100_2') Or  IsNamedPolygon('C100_2') Or  IsNamedPolygon('VBATT') Or  IsNamedPolygon('C102_2') Or  IsNamedPolygon('C100_2') Or  IsNamedPolygon('C100_2') Or  IsNamedPolygon('SGND') Or  IsNamedPolygon('PGND') Or  IsNamedPolygon('PGND') Or  IsNamedPolygon('PGND') Or  IsNamedPolygon('C102_2') Or  IsNamedPolygon('BATT_RTN') Or  IsNamedPolygon('PGND') Or  IsNamedPolygon('CS') Or  IsNamedPolygon('PGND') Or  IsNamedPolygon('VBUS') Or  IsNamedPolygon('J105_1') Or  IsNamedPolygon('PGND') Or  IsNamedPolygon('C102_2') Or  IsNamedPolygon('VBATT') Or  IsNamedPolygon('J105_1') Or  IsNamedPolygon('C103_1') Or  IsNamedPolygon('VBUS') Or  IsNamedPolygon('C103_1') Or  IsNamedPolygon('C103_1') Or  IsNamedPolygon('J105_1') Or  IsNamedPolygon('VBUS') Or  IsNamedPolygon('C122_1') Or  IsNamedPolygon('C103_1') Or  IsNamedPolygon('PGND') Or  IsNamedPolygon('VBUS') Or  IsNamedPolygon('SGND') Or  IsNamedPolygon('RTN') Or  IsNamedPolygon('BATT_RTN') Or  IsNamedPolygon('Q101_2') Or  IsNamedPolygon('C122_2') Or  IsNamedPolygon('C103_1') Or  IsNamedPolygon('PGND') Or  IsNamedPolygon('C100_1') Or  IsNamedPolygon('C122_2') Or  IsNamedPolygon('C100_2') Or  IsNamedPolygon('BATT_RTN') Or  IsNamedPolygon('PGND') Or  IsNamedPolygon('VBATT') Or  IsNamedPolygon('C100_1') Or  IsNamedPolygon('C102_2') Or  IsNamedPolygon('C100_2') Or  IsNamedPolygon('RTN') Or  IsNamedPolygon('VBATT') Or  IsNamedPolygon('C100_1') Or  IsNamedPolygon('VBATT') Or  IsNamedPolygon('C100_1') Or  IsNamedPolygon('C122_1') Or  IsNamedPolygon('VBATT') Or  IsNamedPolygon('PGND') Or  IsNamedPolygon('VBUS') Or  IsNamedPolygon('J105_1') Or  IsNamedPolygon('SGND') Or  IsNamedPolygon('HVBUS') Or  IsNamedPolygon('J105_1') Or  IsNamedPolygon('C100_1') Or  IsNamedPolygon('HVBUS') Or  IsNamedPolygon('Q101_2') Or  IsNamedPolygon('C100_1') Or  IsNamedPolygon('J105_1') Or  IsNamedPolygon('BATT_RTN') Or  IsNamedPolygon('VBUS') Or  IsNamedPolygon('CS') Or  IsNamedPolygon('C100_1') Or  IsNamedPolygon('PGND') Or  IsNamedPolygon('PGND') Or  IsNamedPolygon('Q101_2') Or  IsNamedPolygon('C103_1') Or  IsNamedPolygon('C100_1') Or  IsNamedPolygon('PGND')] p9: connectstyle=Direct reliefconductorwidth=10 reliefentries=4 polygonreliefangle="90 Angle" airgapwidth=10
PolygonConnect PolygonConnect_20 [All vs IsNamedPolygon('CS') Or  IsNamedPolygon('C122_2') Or  IsNamedPolygon('PGND') Or  IsNamedPolygon('C102_2') Or  IsNamedPolygon('HVBUS') Or  IsNamedPolygon('CS') Or  IsNamedPolygon('RTN') Or  IsNamedPolygon('VBUS') Or  IsNamedPolygon('RTN') Or  IsNamedPolygon('C102_2') Or  IsNamedPolygon('C102_2') Or  IsNamedPolygon('VBUS') Or  IsNamedPolygon('C122_1') Or  IsNamedPolygon('C122_2') Or  IsNamedPolygon('C122_1') Or  IsNamedPolygon('Q101_2') Or  IsNamedPolygon('C102_2') Or  IsNamedPolygon('J105_1') Or  IsNamedPolygon('VBATT') Or  IsNamedPolygon('BATT_RTN') Or  IsNamedPolygon('C100_2') Or  IsNamedPolygon('VBATT') Or  IsNamedPolygon('C100_2') Or  IsNamedPolygon('SGND') Or  IsNamedPolygon('J105_1') Or  IsNamedPolygon('C100_1') Or  IsNamedPolygon('BATT_RTN') Or  IsNamedPolygon('C100_1') Or  IsNamedPolygon('C103_1') Or  IsNamedPolygon('C103_1')] p10: connectstyle=Direct reliefconductorwidth=10 reliefentries=4 polygonreliefangle="90 Angle" airgapwidth=10
PolygonConnect PolygonConnect_19 [All vs IsNamedPolygon('C100_1') Or  IsNamedPolygon('C100_1') Or  IsNamedPolygon('VBATT') Or  IsNamedPolygon('VBATT') Or  IsNamedPolygon('C103_1') Or  IsNamedPolygon('C103_1') Or  IsNamedPolygon('C100_2') Or  IsNamedPolygon('C100_2') Or  IsNamedPolygon('RTN') Or  IsNamedPolygon('RTN') Or  IsNamedPolygon('PGND') Or  IsNamedPolygon('C102_2') Or  IsNamedPolygon('C102_2') Or  IsNamedPolygon('C102_2') Or  IsNamedPolygon('C102_2') Or  IsNamedPolygon('CS') Or  IsNamedPolygon('CS') Or  IsNamedPolygon('C122_1') Or  IsNamedPolygon('C122_2') Or  IsNamedPolygon('C122_2') Or  IsNamedPolygon('C122_1') Or  IsNamedPolygon('Q101_2') Or  IsNamedPolygon('HVBUS') Or  IsNamedPolygon('VBUS') Or  IsNamedPolygon('VBUS')] p11: connectstyle=Direct reliefconductorwidth=10 reliefentries=4 polygonreliefangle="90 Angle" airgapwidth=10
PolygonConnect PolygonConnect_18 [All vs IsNamedPolygon('C103_1') Or  IsNamedPolygon('C102_2') Or  IsNamedPolygon('RTN') Or  IsNamedPolygon('PGND') Or  IsNamedPolygon('VBATT') Or  IsNamedPolygon('C100_2') Or  IsNamedPolygon('C102_2') Or  IsNamedPolygon('RTN') Or  IsNamedPolygon('C102_2') Or  IsNamedPolygon('C100_2') Or  IsNamedPolygon('C103_1') Or  IsNamedPolygon('C102_2') Or  IsNamedPolygon('VBATT') Or  IsNamedPolygon('CS') Or  IsNamedPolygon('CS') Or  IsNamedPolygon('C122_2') Or  IsNamedPolygon('C122_1') Or  IsNamedPolygon('VBUS') Or  IsNamedPolygon('C122_2') Or  IsNamedPolygon('Q101_2') Or  IsNamedPolygon('C122_1') Or  IsNamedPolygon('VBUS') Or  IsNamedPolygon('HVBUS')] p12: connectstyle=Direct reliefconductorwidth=10 reliefentries=4 polygonreliefangle="90 Angle" airgapwidth=10
PolygonConnect PolygonConnect_17 [All vs IsNamedPolygon('CS') Or  IsNamedPolygon('C102_2') Or  IsNamedPolygon('C122_2') Or  IsNamedPolygon('C102_2') Or  IsNamedPolygon('C122_1') Or  IsNamedPolygon('C102_2') Or  IsNamedPolygon('Q101_2') Or  IsNamedPolygon('VBUS') Or  IsNamedPolygon('C122_2') Or  IsNamedPolygon('C102_2') Or  IsNamedPolygon('RTN') Or  IsNamedPolygon('C122_1') Or  IsNamedPolygon('VBUS') Or  IsNamedPolygon('RTN') Or  IsNamedPolygon('PGND') Or  IsNamedPolygon('CS') Or  IsNamedPolygon('HVBUS')] p13: connectstyle=Direct reliefconductorwidth=10 reliefentries=4 polygonreliefangle="90 Angle" airgapwidth=10
PolygonConnect PolygonConnect_16 [All vs IsNamedPolygon('C122_2') Or  IsNamedPolygon('CS') Or  IsNamedPolygon('C122_1') Or  IsNamedPolygon('Q101_2') Or  IsNamedPolygon('VBUS') Or  IsNamedPolygon('VBUS') Or  IsNamedPolygon('HVBUS') Or  IsNamedPolygon('C122_2') Or  IsNamedPolygon('C122_1')] p14: connectstyle=Direct reliefconductorwidth=10 reliefentries=4 polygonreliefangle="90 Angle" airgapwidth=10
PolygonConnect PolygonConnect_15 [All vs IsNamedPolygon('C109_2') Or  IsNamedPolygon('C107_2') Or  IsNamedPolygon('HV') Or  IsNamedPolygon('Q203_5') Or  IsNamedPolygon('C107_2') Or  IsNamedPolygon('HS') Or  IsNamedPolygon('Q201_5') Or  IsNamedPolygon('Q203_5') Or  IsNamedPolygon('C106_2') Or  IsNamedPolygon('C108_2') Or  IsNamedPolygon('Vout') Or  IsNamedPolygon('Q203_5') Or  IsNamedPolygon('C108_2') Or  IsNamedPolygon('C113_2') Or  IsNamedPolygon('Q203_5') Or  IsNamedPolygon('Q201_5') Or  IsNamedPolygon('C107_2') Or  IsNamedPolygon('C102_1') Or  IsNamedPolygon('SGND') Or  IsNamedPolygon('GND') Or  IsNamedPolygon('SGND') Or  IsNamedPolygon('GND') Or  IsNamedPolygon('IN+') Or  IsNamedPolygon('IN+') Or  IsNamedPolygon('Q201_5') Or  IsNamedPolygon('Q201_5') Or  IsNamedPolygon('SGND') Or  IsNamedPolygon('SGND') Or  IsNamedPolygon('Vout') Or  IsNamedPolygon('Vout') Or  IsNamedPolygon('IN+') Or  IsNamedPolygon('GND') Or  IsNamedPolygon('IN+') Or  IsNamedPolygon('GND')] p15: connectstyle=Direct reliefconductorwidth=10 reliefentries=4 polygonreliefangle="90 Angle" airgapwidth=10
PolygonConnect PolygonConnect_14 [All vs IsNamedPolygon('C106_2') Or  IsNamedPolygon('C107_2') Or  IsNamedPolygon('C107_2') Or  IsNamedPolygon('C107_2') Or  IsNamedPolygon('C102_1') Or  IsNamedPolygon('Q203_5') Or  IsNamedPolygon('Vout') Or  IsNamedPolygon('Q203_5') Or  IsNamedPolygon('Q203_5') Or  IsNamedPolygon('Q201_5') Or  IsNamedPolygon('C108_2') Or  IsNamedPolygon('Q203_5') Or  IsNamedPolygon('HS') Or  IsNamedPolygon('HV') Or  IsNamedPolygon('C108_2') Or  IsNamedPolygon('Q201_5') Or  IsNamedPolygon('C109_2') Or  IsNamedPolygon('Q201_5') Or  IsNamedPolygon('Q201_5') Or  IsNamedPolygon('C113_2')] p16: connectstyle=Direct reliefconductorwidth=10 reliefentries=4 polygonreliefangle="90 Angle" airgapwidth=10
PolygonConnect PolygonConnect_13 [All vs IsNamedPolygon('C102_1') Or  IsNamedPolygon('HV') Or  IsNamedPolygon('C107_2') Or  IsNamedPolygon('C109_2') Or  IsNamedPolygon('C107_2') Or  IsNamedPolygon('C108_2') Or  IsNamedPolygon('C106_2') Or  IsNamedPolygon('C108_2') Or  IsNamedPolygon('C113_2') Or  IsNamedPolygon('C107_2')] p17: connectstyle=Direct reliefconductorwidth=10 reliefentries=4 polygonreliefangle="90 Angle" airgapwidth=10
PolygonConnect PolygonConnect_12 [All vs IsNamedPolygon('C107_2') Or  IsNamedPolygon('C113_2') Or  IsNamedPolygon('C106_2') Or  IsNamedPolygon('C107_2') Or  IsNamedPolygon('C107_2') Or  IsNamedPolygon('C102_1')] p18: connectstyle=Direct reliefconductorwidth=10 reliefentries=4 polygonreliefangle="90 Angle" airgapwidth=10
PolygonConnect PolygonConnect_11 [All vs IsNamedPolygon('C106_2') Or  IsNamedPolygon('C102_1') Or  IsNamedPolygon('C107_2') Or  IsNamedPolygon('C107_2') Or  IsNamedPolygon('C107_2')] p19: connectstyle=Direct reliefconductorwidth=10 reliefentries=4 polygonreliefangle="90 Angle" airgapwidth=10
PolygonConnect PolygonConnect_10 [All vs IsNamedPolygon('C106_2')] p20: connectstyle=Direct reliefconductorwidth=10 reliefentries=4 polygonreliefangle="90 Angle" airgapwidth=10
PolygonConnect PolygonConnect_9 [All vs IsNamedPolygon('C11_1') Or  IsNamedPolygon('Vin') Or  IsNamedPolygon('Vin') Or  IsNamedPolygon('5V') Or  IsNamedPolygon('D6_2') Or  IsNamedPolygon('Q3_3') Or  IsNamedPolygon('GND2') Or  IsNamedPolygon('GND2') Or  IsNamedPolygon('GND') Or  IsNamedPolygon('Q3_4') Or  IsNamedPolygon('12V5') Or  IsNamedPolygon('GND') Or  IsNamedPolygon('12V5') Or  IsNamedPolygon('D3_1')] p21: connectstyle=Direct reliefconductorwidth=10 reliefentries=4 polygonreliefangle="90 Angle" airgapwidth=10
PolygonConnect PolygonConnect_8 [All vs IsNamedPolygon('C11_1') Or  IsNamedPolygon('Vin') Or  IsNamedPolygon('12V5') Or  IsNamedPolygon('Q3_3') Or  IsNamedPolygon('GND2') Or  IsNamedPolygon('GND2') Or  IsNamedPolygon('5V') Or  IsNamedPolygon('Q3_4') Or  IsNamedPolygon('12V5')] p22: connectstyle=Direct reliefconductorwidth=10 reliefentries=4 polygonreliefangle="90 Angle" airgapwidth=10
PolygonConnect PolygonConnect_7 [All vs IsNamedPolygon('GND2') Or  IsNamedPolygon('GND2') Or  IsNamedPolygon('5V') Or  IsNamedPolygon('12V5') Or  IsNamedPolygon('12V5') Or  IsNamedPolygon('C11_1')] p23: connectstyle=Direct reliefconductorwidth=10 reliefentries=4 polygonreliefangle="90 Angle" airgapwidth=10
PolygonConnect PolygonConnect_6 [All vs IsNamedPolygon('GND2') Or  IsNamedPolygon('SGND') Or  IsNamedPolygon('GND1') Or  IsNamedPolygon('C901_1') Or  IsNamedPolygon('SGND') Or  IsNamedPolygon('GND2') Or  IsNamedPolygon('GND1')] p24: connectstyle=Direct reliefconductorwidth=10 reliefentries=4 polygonreliefangle="90 Angle" airgapwidth=10
PolygonConnect PolygonConnect_5 [All vs IsNamedPolygon('GND1') Or  IsNamedPolygon('GND1')] p25: connectstyle=Direct reliefconductorwidth=10 reliefentries=4 polygonreliefangle="90 Angle" airgapwidth=10
PolygonConnect PolygonConnect_4 [All vs IsNamedPolygon('C21_1') Or  IsNamedPolygon('C5_1') Or  IsNamedPolygon('C12_2') Or  IsNamedPolygon('C2_2') Or  IsNamedPolygon('C13_1') Or  IsNamedPolygon('C28_1') Or  IsNamedPolygon('C6_1') Or  IsNamedPolygon('GND') Or  IsNamedPolygon('GND2') Or  IsNamedPolygon('C14_1') Or  IsNamedPolygon('C13_1') Or  IsNamedPolygon('Q1_3') Or  IsNamedPolygon('C14_1') Or  IsNamedPolygon('C5_1') Or  IsNamedPolygon('GND2') Or  IsNamedPolygon('C28_1') Or  IsNamedPolygon('D5_2') Or  IsNamedPolygon('D6_2') Or  IsNamedPolygon('D2_1') Or  IsNamedPolygon('C12_2') Or  IsNamedPolygon('D2_1') Or  IsNamedPolygon('C4_1') Or  IsNamedPolygon('C4_1') Or  IsNamedPolygon('C2_2') Or  IsNamedPolygon('GND') Or  IsNamedPolygon('C33_1') Or  IsNamedPolygon('C9_1')] p26: connectstyle=Direct reliefconductorwidth=10 reliefentries=4 polygonreliefangle="90 Angle" airgapwidth=10
PolygonConnect PolygonConnect_3 [All vs IsNamedPolygon('C28_1') Or  IsNamedPolygon('C12_2') Or  IsNamedPolygon('C28_1') Or  IsNamedPolygon('C9_1') Or  IsNamedPolygon('D5_2') Or  IsNamedPolygon('C12_2') Or  IsNamedPolygon('C2_2') Or  IsNamedPolygon('C14_1') Or  IsNamedPolygon('C4_1') Or  IsNamedPolygon('C14_1') Or  IsNamedPolygon('D6_2') Or  IsNamedPolygon('GND2') Or  IsNamedPolygon('Q1_3') Or  IsNamedPolygon('C5_1') Or  IsNamedPolygon('D2_1') Or  IsNamedPolygon('C4_1') Or  IsNamedPolygon('C13_1') Or  IsNamedPolygon('C5_1') Or  IsNamedPolygon('C13_1') Or  IsNamedPolygon('C33_1') Or  IsNamedPolygon('D2_1') Or  IsNamedPolygon('GND') Or  IsNamedPolygon('GND') Or  IsNamedPolygon('GND2') Or  IsNamedPolygon('C2_2') Or  IsNamedPolygon('C6_1') Or  IsNamedPolygon('C21_1')] p27: connectstyle=Direct reliefconductorwidth=10 reliefentries=4 polygonreliefangle="90 Angle" airgapwidth=10
PolygonConnect PolygonConnect_2 [All vs IsNamedPolygon('C21_1') Or  IsNamedPolygon('C4_1') Or  IsNamedPolygon('D5_2') Or  IsNamedPolygon('C5_1') Or  IsNamedPolygon('C14_1') Or  IsNamedPolygon('C13_1') Or  IsNamedPolygon('C4_1') Or  IsNamedPolygon('C33_1') Or  IsNamedPolygon('C12_2') Or  IsNamedPolygon('D2_1') Or  IsNamedPolygon('C2_2') Or  IsNamedPolygon('C28_1') Or  IsNamedPolygon('C12_2') Or  IsNamedPolygon('D2_1') Or  IsNamedPolygon('C5_1') Or  IsNamedPolygon('Q1_3') Or  IsNamedPolygon('GND') Or  IsNamedPolygon('D6_2') Or  IsNamedPolygon('C6_1') Or  IsNamedPolygon('C2_2') Or  IsNamedPolygon('C14_1') Or  IsNamedPolygon('C28_1') Or  IsNamedPolygon('C13_1') Or  IsNamedPolygon('C9_1') Or  IsNamedPolygon('GND')] p28: connectstyle=Direct reliefconductorwidth=10 reliefentries=4 polygonreliefangle="90 Angle" airgapwidth=10
PolygonConnect PolygonConnect_1 [All vs IsNamedPolygon('C28_1') Or  IsNamedPolygon('D5_2') Or  IsNamedPolygon('C5_1') Or  IsNamedPolygon('C5_1') Or  IsNamedPolygon('D2_1') Or  IsNamedPolygon('C21_1') Or  IsNamedPolygon('C9_1') Or  IsNamedPolygon('C4_1') Or  IsNamedPolygon('C14_1') Or  IsNamedPolygon('C28_1') Or  IsNamedPolygon('C6_1') Or  IsNamedPolygon('C12_2') Or  IsNamedPolygon('C33_1') Or  IsNamedPolygon('C4_1') Or  IsNamedPolygon('C13_1') Or  IsNamedPolygon('C12_2') Or  IsNamedPolygon('D6_2') Or  IsNamedPolygon('C2_2') Or  IsNamedPolygon('C14_1') Or  IsNamedPolygon('D2_1') Or  IsNamedPolygon('C2_2') Or  IsNamedPolygon('C13_1')] p29: connectstyle=Direct reliefconductorwidth=10 reliefentries=4 polygonreliefangle="90 Angle" airgapwidth=10
PolygonConnect [All] p30: connectstyle=Relief reliefconductorwidth=10 reliefentries=4 polygonreliefangle="90 Angle" airgapwidth=10
RoutingVias ThermalPadVias [IsVia and InAnyComponent] p1: holewidth=7.87 width=19.68 viastyle="Through Hole" minholewidth=7.87 minwidth=19.68 maxholewidth=12.99 maxwidth=23.62
RoutingVias [All] p2: holewidth=16 width=34 viastyle="Through Hole" minholewidth=7.87 minwidth=20 maxholewidth=40 maxwidth=65
SilkToBoardRegionClearance [Not ((IsComment or IsDesignator) And (Hide <> 'False')) and not InRegion(1000,500,4000,800)] p1:
SilkToSilkClearance SilkToSilkClearance_Pb-FreeLogo [(HasFootprint('Pb-Free_Overlay_Medium') OR HasFootprint('Pb-Free_Overlay_Small')) vs (HasFootprint('Pb-Free_Overlay_Medium') OR HasFootprint('Pb-Free_Overlay_Small'))] p1: silktosilkclearance=0
SilkToSilkClearance [All] p2: silktosilkclearance=1
SilkToSolderMaskClearance "Silk to Solder Mask Opening" [All] p1: minsilkscreentomaskgap=1 clearancetoexposedcopper=FALSE
SolderMaskExpansion [All] p1: expansion=1.97
Width [All] p1: maxlimit=100 minlimit=6 preferedwidth=10 checkconnectedcopper=TRUE
14 further rules are at their usual default settings.

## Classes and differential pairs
component class Header: J201
component class "Mounting Holes": H201 H203 H205 H207
net class MV: NetR240_1
net class HV: HVBUS Leg_1_Prim Leg_1_Sec Leg_2_Prim Leg_2_Sec NetC101_2 NetC102_2 NetR100_1 NetR101_1 NetR110_1 NetR111_1 VBATT VBUS VOUT
component class Controller: C200 C201 C202 C203 C204 C205 C206 C207 C208 C209 C210 C211 C214 C215 C216 C217 C218 C219 C220 C221 C222 C223 C224 C225 C226 C227 C228 C229 C230 C231 C232 C233 C234 C235 C236 C237 C238 C239 C240 C241 C242 C243 C244 C245 C246 D200 H200 H201 H202 H203 H204 H205 H206 H207 J200 J201 J202 J203 J204 R200 R201 R202 R203 R204 R205 R206 R207 R208 R209 R210 R211 R212 R213 R214 R215 R216 R217 R218 R219 R220 R221 R224 R227 R228 R229 R230 R231 R232 R233 R234 R235 R236 R237 R238 R239 R240 R241 R242 R243 R244 R245 R246 R247 R248 R249 R250 R251 R252 R253 R254 R255 R256 R257 R258 R259 R260 R261 TP200 TP201 U200 U201 U202 U203 U204 U205 U206 U207 U208 U209
component class PowerStage: !PCB100 C100 C101 C102 C103 C104 C105 C106 C107 C108 C109 C110 C111 C112 C113 C114 C115 C120 C121 C122 C123 C124 C126 C127 C128 C129 C130 C131 C132 C133 C134 C135 C136 C137 C138 C139 C141 C143 C145 C147 F100 F101 H100 H101 H102 H103 H104 H105 H106 H107 J100 J101 J102 J103 J104 J105 J106 J107 J108 J109 J110 J111 LOGO100 Logo101 Logo102 Logo103 LOGO104 LOGO105 QPL1H_D QPL1H_S QPL1L_D QPL1L_S QPL2H_D QPL2H_S QPL2L_D QPL2L_S QSL1H_D QSL1H_S QSL1L_D QSL1L_S QSL2H_D QSL2H_S QSL2L_D QSL2L_S R100 R101 R102 R103 R104 R105 R106 R107 R108 R109 R110 R111 R112 R113 R114 R115 R116 R117 R118 R119 R120 R121 R122 T100 TP100 TP101 TP102 TP103 TP104 TP105 TP106 XF100 XF101 XF102 XF103
net class HV_XFMR: Crp_1 Crs_1 NetC100_2 NetC127_1

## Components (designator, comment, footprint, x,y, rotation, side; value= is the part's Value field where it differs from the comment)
C100 "" 1206_190 5992.41,1930.63 r90 top value=8200pF
C101 "400BXW150MEFC16X45" FC_1600x4000 3280,860 r90 top value=150uF
C102 "400BXW150MEFC16X45" FC_1600x4000 3280,2320 r90 top value=150uF
C103 "500MXG150MEFCSN22X55" Nichicon_2200x4500_Snap 8906.4,3280 r270 top value=150uF
C104 "500MXG150MEFCSN22X55" Nichicon_2200x4500_Snap 8840,2347.01 r270 top value=150uF
C105 "" 1206_190 6080,1930.63 r90 top value=8200pF
C106 "500MXG150MEFCSN22X55" Nichicon_2200x4500_Snap 8840,1406.85 r270 top value=150uF
C107 "500MXG150MEFCSN22X55" Nichicon_2200x4500_Snap 8840,466.69 r270 top value=150uF
C108 "" 1206_190 6170,1930.63 r90 top value=8200pF
C109 "" 1206_190 6260,1930.63 r90 top value=8200pF
C110 "" 1206_190 6350,1930 r90 top value=8200pF
C111 "400BXW150MEFC16X45" FC_1600x4000 3280,1650 r90 top value=150uF
C112 "400BXW150MEFC16X45" FC_1600x4000 3280,3111.1 r90 top value=150uF
C113 "" 1206_190 6440,1930 r90 top value=8200pF
C114 "" 1206_190 6530,1930 r90 top value=8200pF
C115 "" 1206_190 6620,1930 r90 top value=8200pF
C120 "1812Y1K00104KXT" 1812_254 3789.01,1203.94 r180 top value=0.1uF
C121 "1812Y1K00104KXT" 1812_254 3789.01,1357.01 r180 top value=0.1uF
C122 "" 1206_190 5980,1930 r90 bottom value=8200pF
C123 "B58031I5105M002" B58031I_1084x785x450 7680,2800 r0 top value=1uF
C124 "B58031I5105M002" B58031I_1084x785x450 7680,1330 r0 top value=1uF
C126 "" 1206_190 6070,1930 r90 bottom value=8200pF
C127 "" 1206_190 5330.6,1930 r270 top value=8200pF
C128 "" 1206_190 6160,1930 r90 bottom value=8200pF
C129 "" 1206_190 5420.6,1930 r270 top value=8200pF
C130 "" 1206_190 6250,1930 r90 bottom value=8200pF
C131 "" 1206_190 5510.6,1930 r270 top value=8200pF
C132 "" 1206_190 6340,1930 r90 bottom value=8200pF
C133 "" 1206_190 5600.6,1930 r270 top value=8200pF
C134 "" 1206_190 6430,1930 r90 bottom value=8200pF
C135 "" 1206_190 5690.6,1930 r270 top value=8200pF
C136 "" 1206_190 6520,1930 r90 bottom value=8200pF
C137 "" 1206_190 5330.6,1930 r270 bottom value=8200pF
C138 "" 1206_190 6610,1930 r90 bottom value=8200pF
C139 "" 1206_190 5420.6,1930 r270 bottom value=8200pF
C141 "" 1206_190 5510.6,1930 r270 bottom value=8200pF
C143 "" 1206_190 5600.6,1930 r270 bottom value=8200pF
C145 "" 1206_190 5690.6,1930 r270 bottom value=8200pF
C147 "DE1E3KX222MA4BL01" CAPRD1000W60D900H1200 6120,100 r180 top value=2200pF
C200 "C0402C100C8GACTU" 0402 6208,4741.87 r180 top value=10pF
C201 "06033C104JAT2A" 0603 4328.52,4337.51 r0 top value=0.1uF
C202 "GRM188C80J225KE19D" 0603 7108,4861.87 r270 top value=2.2uF
C203 "C0402C222K9RAC7867" 0402 6408,5251.87 r0 top value=2200pF
C204 "AC0402KRX7R9BB221" 0402 6448,4901.87 r0 bottom value=220pF
C205 "06033C104JAT2A" 0603 6448,4841.87 r0 bottom value=0.1uF
C206 "06033C104JAT2A" 0603 6442.41,4752.86 r180 top value=0.1uF
C207 "C1005X7R1E104M050BB" 0402 6308,4741.87 r180 top value=0.1uF
C208 "C0603C100J5GACTU" 0603 6268,5159 r0 top value=10pF
C209 "06033C104JAT2A" 0603 6148,5159 r180 top value=0.1uF
C210 "C0402C100C8GACTU" 0402 6008,4741.87 r180 top value=10pF
C211 "C0402C100C8GACTU" 0402 6108,4741.87 r180 top value=10pF
C214 "C1608X7R1E105K080AB" 0603 6148,5509 r0 top value=1uF
C215 "CC0402KRX7R5BB104" 0402 6218,5609 r90 top value=0.1uF
C216 "06033C104JAT2A" 0603 6608,5649 r0 top value=0.1uF
C217 "CC0402KRX7R5BB104" 0402 6018,5649 r270 top value=0.1uF
C218 "06033C104JAT2A" 0603 6478,5649 r180 top value=0.1uF
C219 "06033C104JAT2A" 0603 6538,5409 r180 top value=0.1uF
C220 "GRM155R61A103KA01D" 0402 6068.95,5366.13 r270 top value=0.01uF
C221 "GRM1555C1H2R2BA01D" 0402 6078,4339.59 r0 top value=2.2pF
C222 "C1608X7R1E105K080AB" 0603 8906.4,4663.54 r270 top value=1uF
C223 "CGB3B1X5R1A475K055AC" 0603 8756.4,5293.54 r0 top value=4.7uF
C224 "06033C104JAT2A" 0603 8756.4,5233.54 r180 top value=0.1uF
C225 "C1005X7R1E104M050BB" 0402 5975.33,5226.13 r180 top value=0.1uF
C226 "0402YC104KAT2A" 0402 6068,4564.75 r180 top value=0.1uF
C227 "CGA2B2X7R1H222K050BA" 0402 5948,4321.87 r180 top value=2200pF
C228 "06031C103KAT2A" 0603 8756.4,4613.54 r0 top value=0.01uF
C229 "GRM155R61A103KA01D" 0402 5838,5449 r0 top value=0.01uF
C230 "GRM155R61A103KA01D" 0402 5950.87,5499 r0 top value=0.01uF
C231 "0402YC104KAT2A" 0402 5948,4441.87 r90 top value=0.1uF
C232 "GRM155R61A103KA01D" 0402 6702.41,4602.86 r270 top value=0.01uF
C233 "GRM1555C1H2R2BA01D" 0402 6041.37,5183.76 r90 bottom value=2.2pF
C234 "08053C104JAT2A" 0805_HV 6328,4501.87 r180 top value=0.1uF
C235 "C1608X7R1E105K080AB" 0603 8386.4,4623.54 r0 top value=1uF
C236 "CGB3B1X5R1A475K055AC" 0603 8516.4,5293.54 r0 top value=4.7uF
C237 "06033C104JAT2A" 0603 8516.4,5233.54 r180 top value=0.1uF
C238 "C1005X7R1E104M050BB" 0402 6622.41,4732.86 r180 top value=0.1uF
C239 "0402YC104KAT2A" 0402 6278,5181.87 r270 bottom value=0.1uF
C240 "CGA2B2X7R1H222K050BA" 0402 5998,5021.87 r270 bottom value=2200pF
C241 "CGA2B2X7R1H471K050BA" 0402 6238,4571.87 r0 top value=470pF
C242 "06031C103KAT2A" 0603 8516.4,4623.54 r0 top value=0.01uF
C243 "GRM155R61A103KA01D" 0402 6592.41,4429.1 r180 top value=0.01uF
C244 "GRM155R61A103KA01D" 0402 6482.41,4602.86 r90 top value=0.01uF
C245 "0402YC104KAT2A" 0402 6158,5062.29 r0 bottom value=0.1uF
C246 "C0402C100C8GACTU" 0402 6258,5021.87 r0 bottom value=10pF
D200 "BAT54S-7-F" SOT-23 7218,4871.87 r90 top value=30V
H200 "1902C" Keystone_1902C 2611.78,1109.3 r180 bottom
H201 "NY PMS 440 0025 PH" "NY PMS 440 0025 PH" 2612.01,1109.29 r0 top
H202 "1902C" Keystone_1902C 9580,1124.88 r180 bottom
H203 "NY PMS 440 0025 PH" "NY PMS 440 0025 PH" 9580,1124.88 r0 top
H204 "1902C" Keystone_1902C 9402.05,5400.01 r180 bottom
H205 "NY PMS 440 0025 PH" "NY PMS 440 0025 PH" 9402.28,5400 r0 top
H206 "1902C" Keystone_1902C 3049,5391.87 r180 bottom
H207 "NY PMS 440 0025 PH" "NY PMS 440 0025 PH" 3049,5391.87 r0 top
J100 "282856-2" TE_282856-2 2623.46,3110 r270 top
J101 "282856-3" TE_282856-3 9616.4,3183.54 r90 top
J102 "282856-3" TE_282856-3 9616.4,4233.54 r90 top
J103 "282856-2" TE_282856-2 2623.46,3864.96 r270 top
J104 "MTMM-102-09-G-D-315" FP-MTMM-102-09-G-D-315_HDR4-MFG 3587.09,2742.76 r270 top locked
J105 "MTMM-104-09-G-D-320" FP-MTMM-104-09-G-D-320_HDR8-MFG 4120.55,3545.62 r0 top locked
J106 "MTMM-102-09-G-D-315" FP-MTMM-102-09-G-D-315_HDR4-MFG 3587.09,1272.68 r270 top locked
J107 "MTMM-104-09-G-D-320" FP-MTMM-104-09-G-D-320_HDR8-MFG 4120.55,2075.55 r0 top locked
J108 "MTMM-104-09-G-D-320" FP-MTMM-104-09-G-D-320_HDR8-MFG 8230,2049.92 r0 top locked
J109 "MTMM-104-09-G-D-320" FP-MTMM-104-09-G-D-320_HDR8-MFG 8230,3520 r0 top locked
J110 "MTMM-102-09-G-D-315" FP-MTMM-102-09-G-D-315_HDR4-MFG 5690,4660 r0 bottom
J111 "MTMM-102-09-G-D-315" FP-MTMM-102-09-G-D-315_HDR4-MFG 5485,4660 r0 bottom
J200 "HSEC8-160-01-L-DV-A-BL" controlCARD-120HSEC 5672.41,4952.86 r180 top locked
J201 "61300511021" Wurth_61300511021 4918,5632.62 r180 top
J202 "HSEC8-130-01-L-DV-A" controlCARD-180HSEC-60pinAddon 3324.26,4952.86 r180 top locked
J203 "SSW-104-24-G-D" Samtec_SSW-104-24-x-D 8019.78,4546.48 r90 top
J204 "215307-3" TE_215307-3 8019.78,5396.48 r90 top
LOGO100 "CAUTION HOT SURFACE" IEC_HotSurface_Medium 7400,330 r0 top
Logo101 "Pb-Free Symbol" Pb-Free_Overlay_Medium 9119.94,4821.28 r0 top
Logo102 "FCC disclaimer" FCC_disclaimer 2530,5199 r90 top
Logo103 "WEEE logo" WEEE_Minimum 9359.94,4851.79 r0 top
LOGO104 "DANGER HIGH VOLTAGE" IEC_HighVoltage_Medium 8030,324 r0 top
LOGO105 "DANGER HIGH VOLTAGE" IEC_HighVoltage_Medium 4620,303.46 r0 top
QPL1H_D "Suggest using a net name here" Mill-Max_0312-0-15-15-34-27-10-0 4641.17,2167.09 r90 bottom locked
QPL1H_S "Suggest using a net name here" Mill-Max_0312-0-15-15-34-27-10-0 4641.17,2367.09 r90 bottom locked
QPL1L_D "Suggest using a net name here" Mill-Max_0312-0-15-15-34-27-10-0 4641.17,2902.12 r90 bottom locked
QPL1L_S "Suggest using a net name here" Mill-Max_0312-0-15-15-34-27-10-0 4641.17,3102.12 r90 bottom locked
QPL2H_D "Suggest using a net name here" Mill-Max_0312-0-15-15-34-27-10-0 4641.17,697.01 r90 bottom
QPL2H_S "Suggest using a net name here" Mill-Max_0312-0-15-15-34-27-10-0 4641.17,897.01 r90 bottom
QPL2L_D "Suggest using a net name here" Mill-Max_0312-0-15-15-34-27-10-0 4641.17,1432.05 r90 bottom locked
QPL2L_S "Suggest using a net name here" Mill-Max_0312-0-15-15-34-27-10-0 4641.17,1632.05 r90 bottom locked
QSL1H_D "Suggest using a net name here" Mill-Max_0312-0-15-15-34-27-10-0 7500,1094.88 r90 bottom locked
QSL1H_S "Suggest using a net name here" Mill-Max_0312-0-15-15-34-27-10-0 7500,894.88 r90 bottom locked
QSL1L_D "Suggest using a net name here" Mill-Max_0312-0-15-15-34-27-10-0 7500,1829.92 r90 bottom locked
QSL1L_S "Suggest using a net name here" Mill-Max_0312-0-15-15-34-27-10-0 7500,1629.92 r90 bottom locked
QSL2H_D "Suggest using a net name here" Mill-Max_0312-0-15-15-34-27-10-0 7500,2564.96 r90 bottom locked
QSL2H_S "Suggest using a net name here" Mill-Max_0312-0-15-15-34-27-10-0 7500,2364.96 r90 bottom locked
QSL2L_D "Suggest using a net name here" Mill-Max_0312-0-15-15-34-27-10-0 7500,3300 r90 bottom locked
QSL2L_S "Suggest using a net name here" Mill-Max_0312-0-15-15-34-27-10-0 7500,3100 r90 bottom locked
R100 "CRCW12061M00FKEA" 1206 3173.23,780 r270 bottom value=1.00Meg
R101 "CRCW12061M00FKEA" 1206 3168.23,2240 r270 bottom value=1.00Meg
R102 "PMR18EZPFU6L00" CSNL1206 8982.79,4244.19 r270 top value=0.006
R103 "WSLP1206R0100FEA" 1206 3143.46,3561.1 r90 top value=0.01
R104 "PMR18EZPFU6L00" CSNL1206 9342.79,4244.19 r270 top value=0.006
R105 "CRCW12061M00FKEA" 1206 3066.3,950 r270 bottom value=1.00Meg
R106 "CRCW12061M00FKEA" 1206 3060,2410 r270 bottom value=1.00Meg
R107 "WSLP1206R0100FEA" 1206 3043.46,3561.1 r90 top value=0.01
R108 "PMR18EZPFU6L00" CSNL1206 9252.79,4244.19 r270 top value=0.006
R109 "WSLP1206R0100FEA" 1206 3243.46,3561.1 r90 top value=0.01
R110 "CRCW12061M00FKEA" 1206 3173.23,1570 r270 bottom value=1.00Meg
R111 "CRCW12061M00FKEA" 1206 3163.46,3030 r270 bottom value=1.00Meg
R112 "PMR18EZPFU6L00" CSNL1206 9162.79,4244.19 r270 top value=0.006
R113 "WSLP1206R0100FEA" 1206 3443.46,3561.1 r90 top value=0.01
R114 "CRCW12061M00FKEA" 1206 3067.48,1737.43 r270 bottom value=1.00Meg
R115 "CRCW12061M00FKEA" 1206 3059.21,3200 r270 bottom value=1.00Meg
R116 "PMR18EZPFU6L00" CSNL1206 9072.79,4243.58 r270 top value=0.006
R117 "WSLP1206R0100FEA" 1206 3343.46,3561.1 r90 top value=0.01
R118 "WSLP1206R0100FEA" 1206 3877.95,3205.51 r0 top value=0.01
R119 "WSLP1206R0100FEA" 1206 3877.95,3305.51 r0 top value=0.01
R120 "WSLP1206R0100FEA" 1206 3877.95,3105.51 r0 top value=0.01
R121 "WSLP1206R0100FEA" 1206 3877.95,2905.51 r0 top value=0.01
